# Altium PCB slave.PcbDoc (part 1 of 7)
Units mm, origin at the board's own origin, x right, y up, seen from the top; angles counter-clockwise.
Board outline 160 x 100 mm, 6 copper layers (Top, FUSED_VBAT-, Signals1, Signals2, SUPPLY, Bottom), stack 1.67 mm thick; 597 components, 381 nets, 1695 pads, 3028 vias.
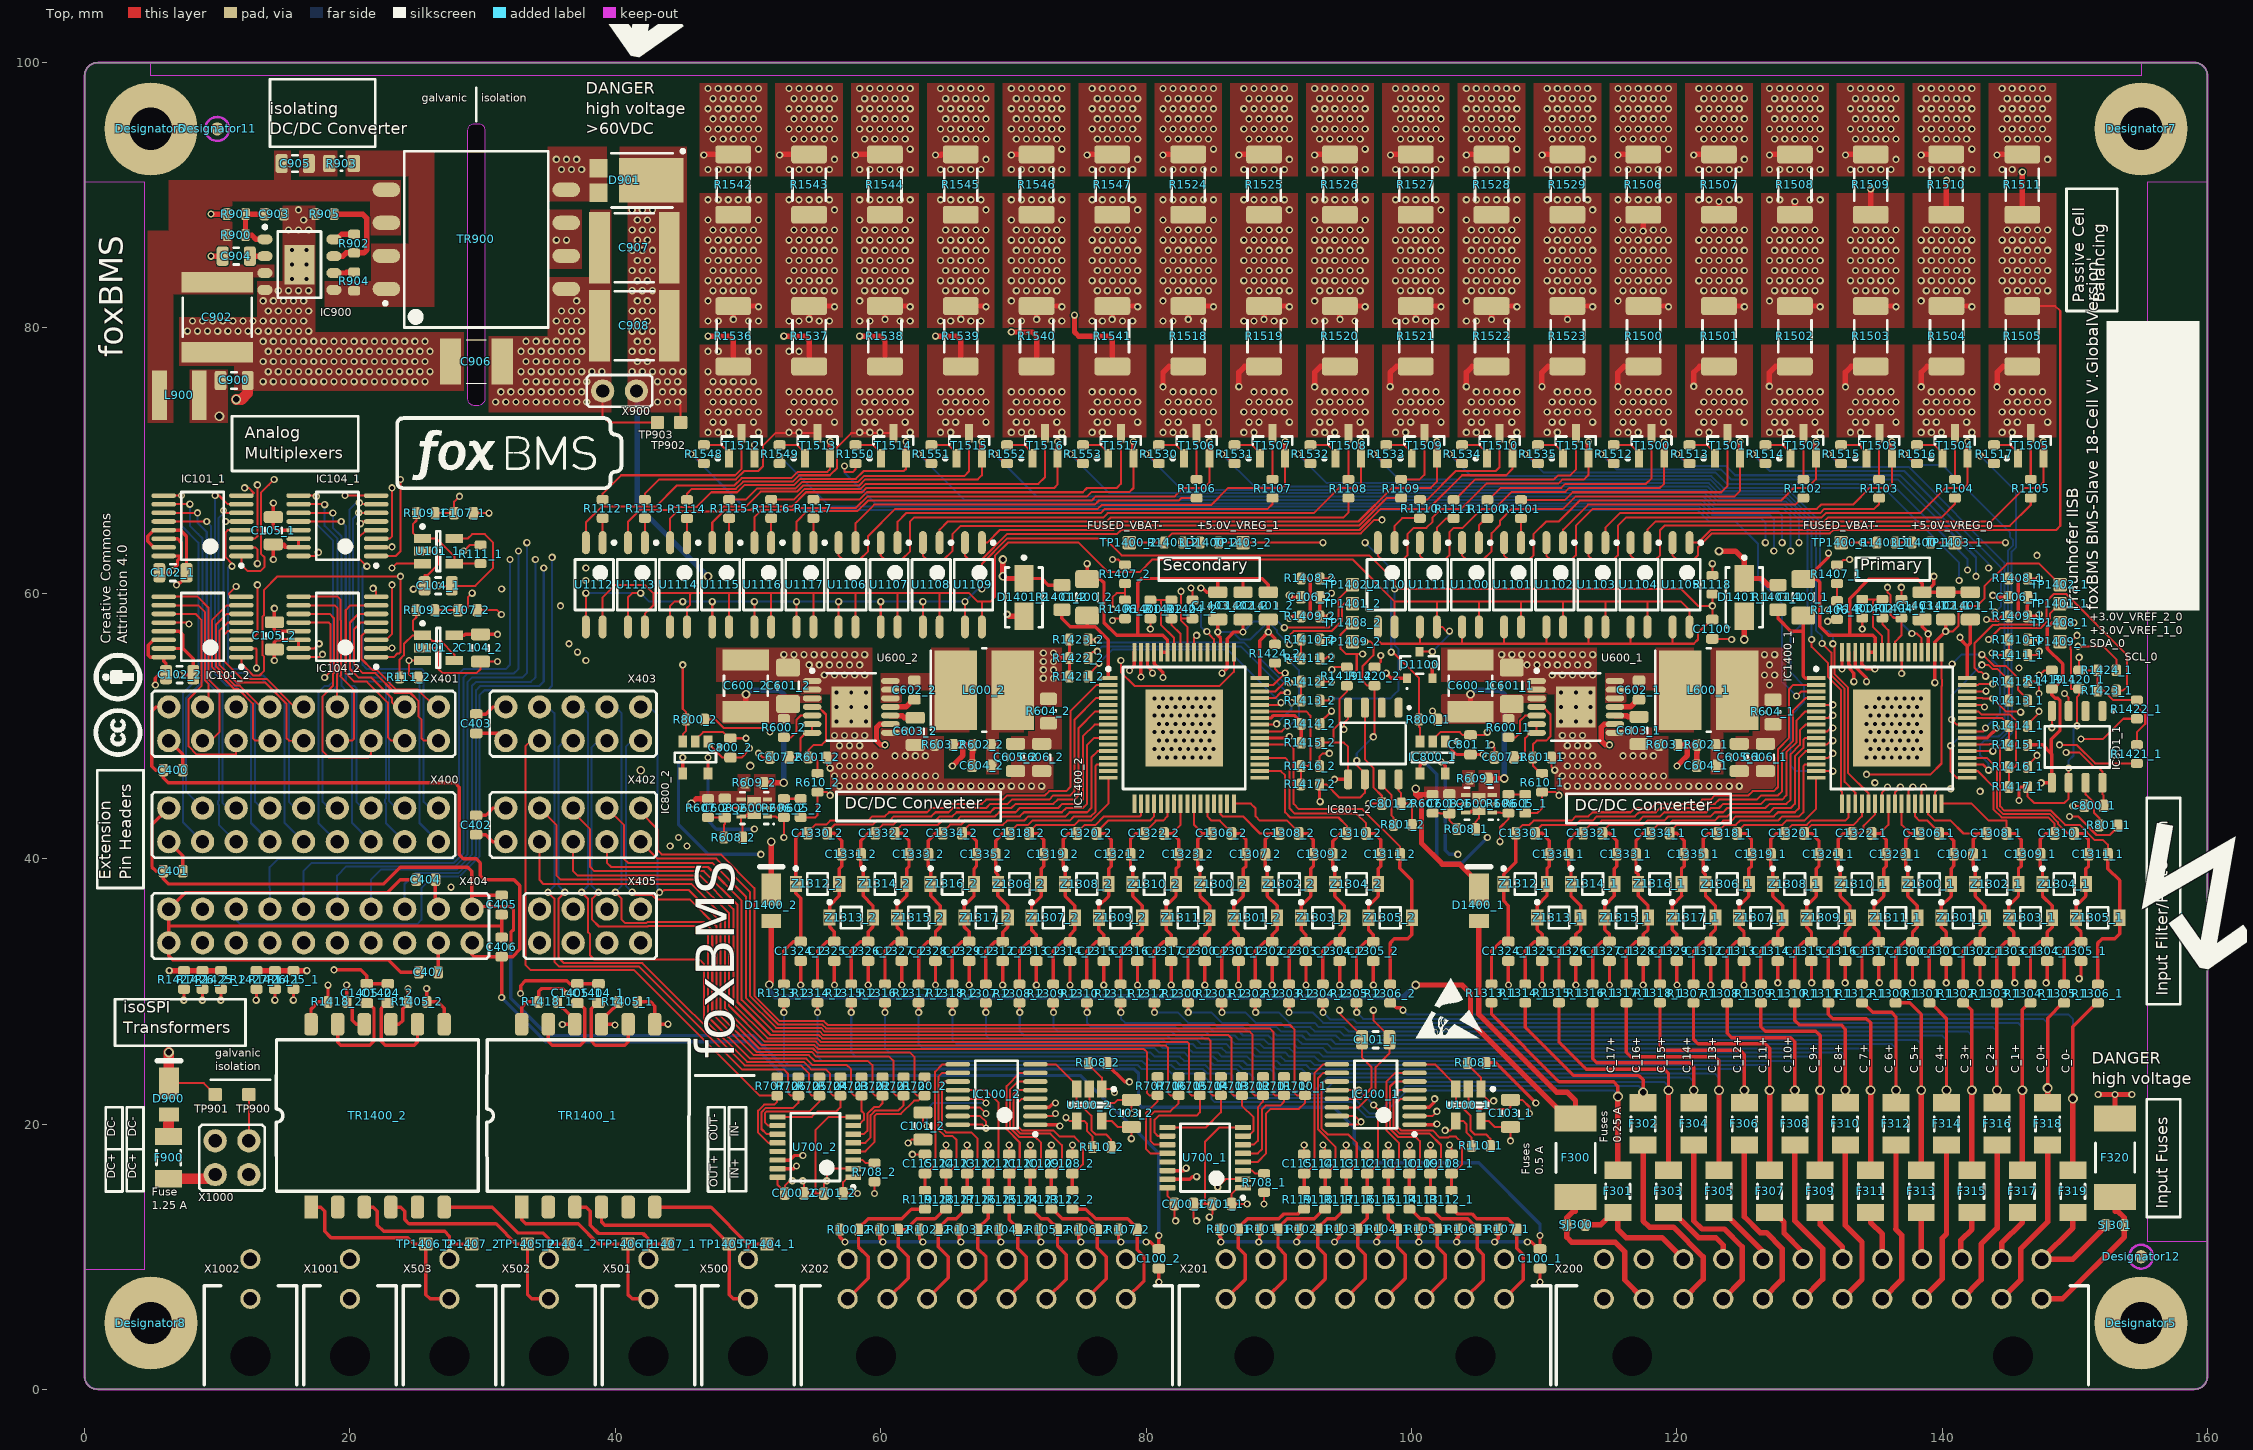
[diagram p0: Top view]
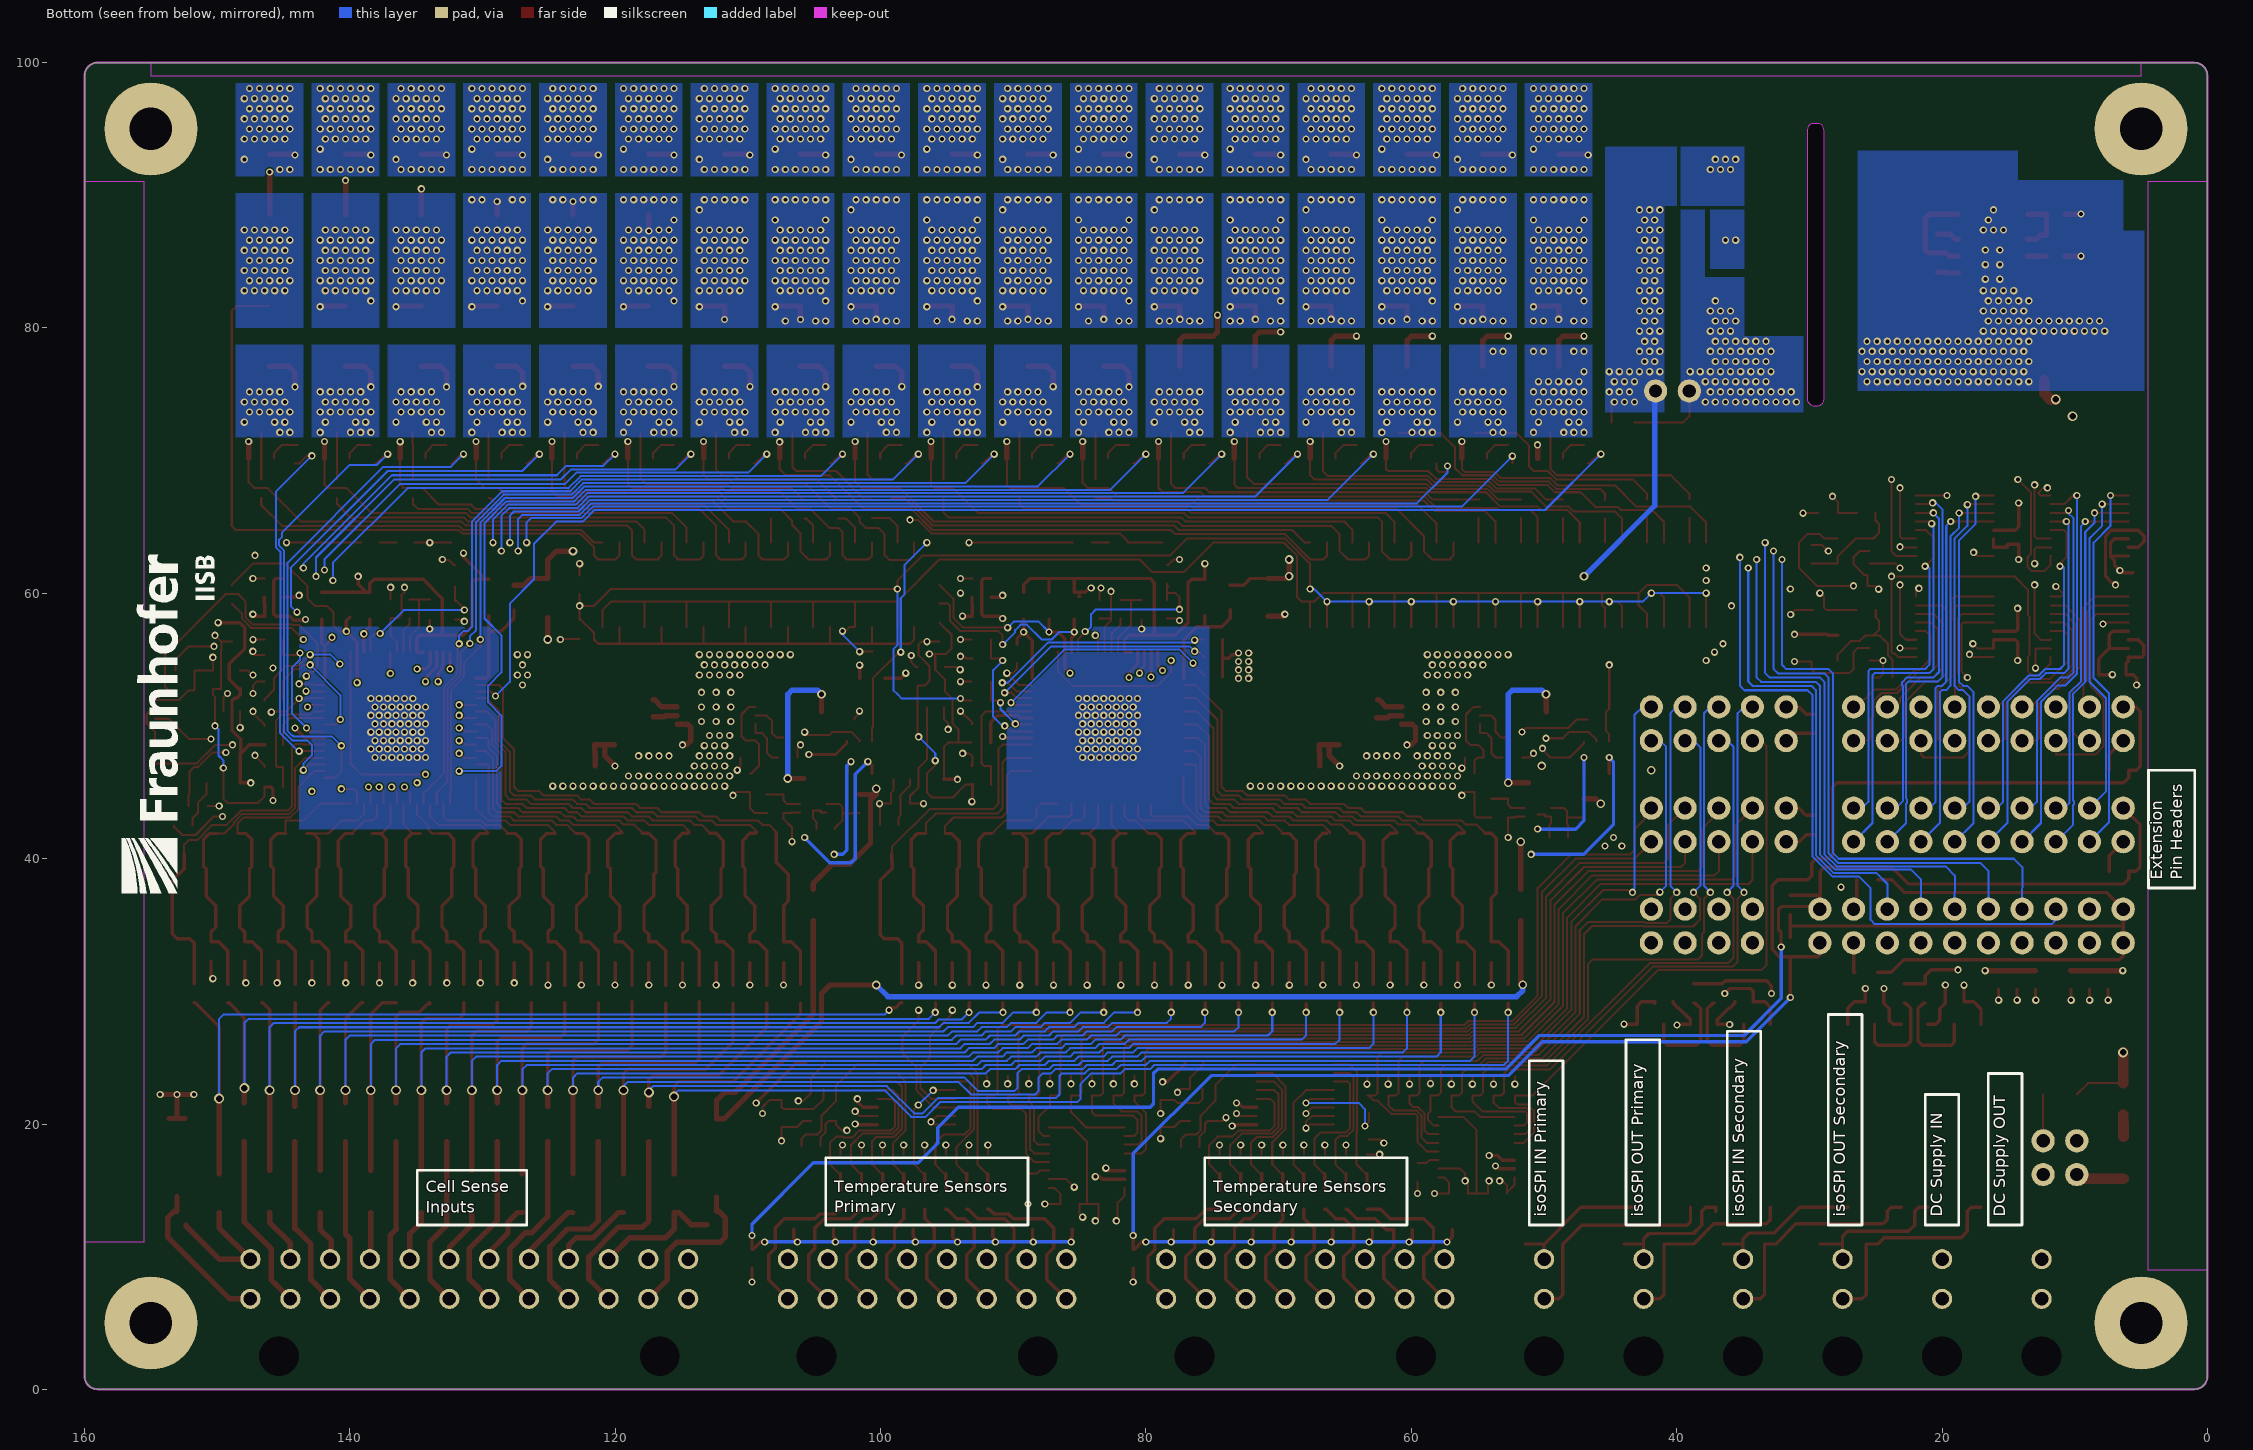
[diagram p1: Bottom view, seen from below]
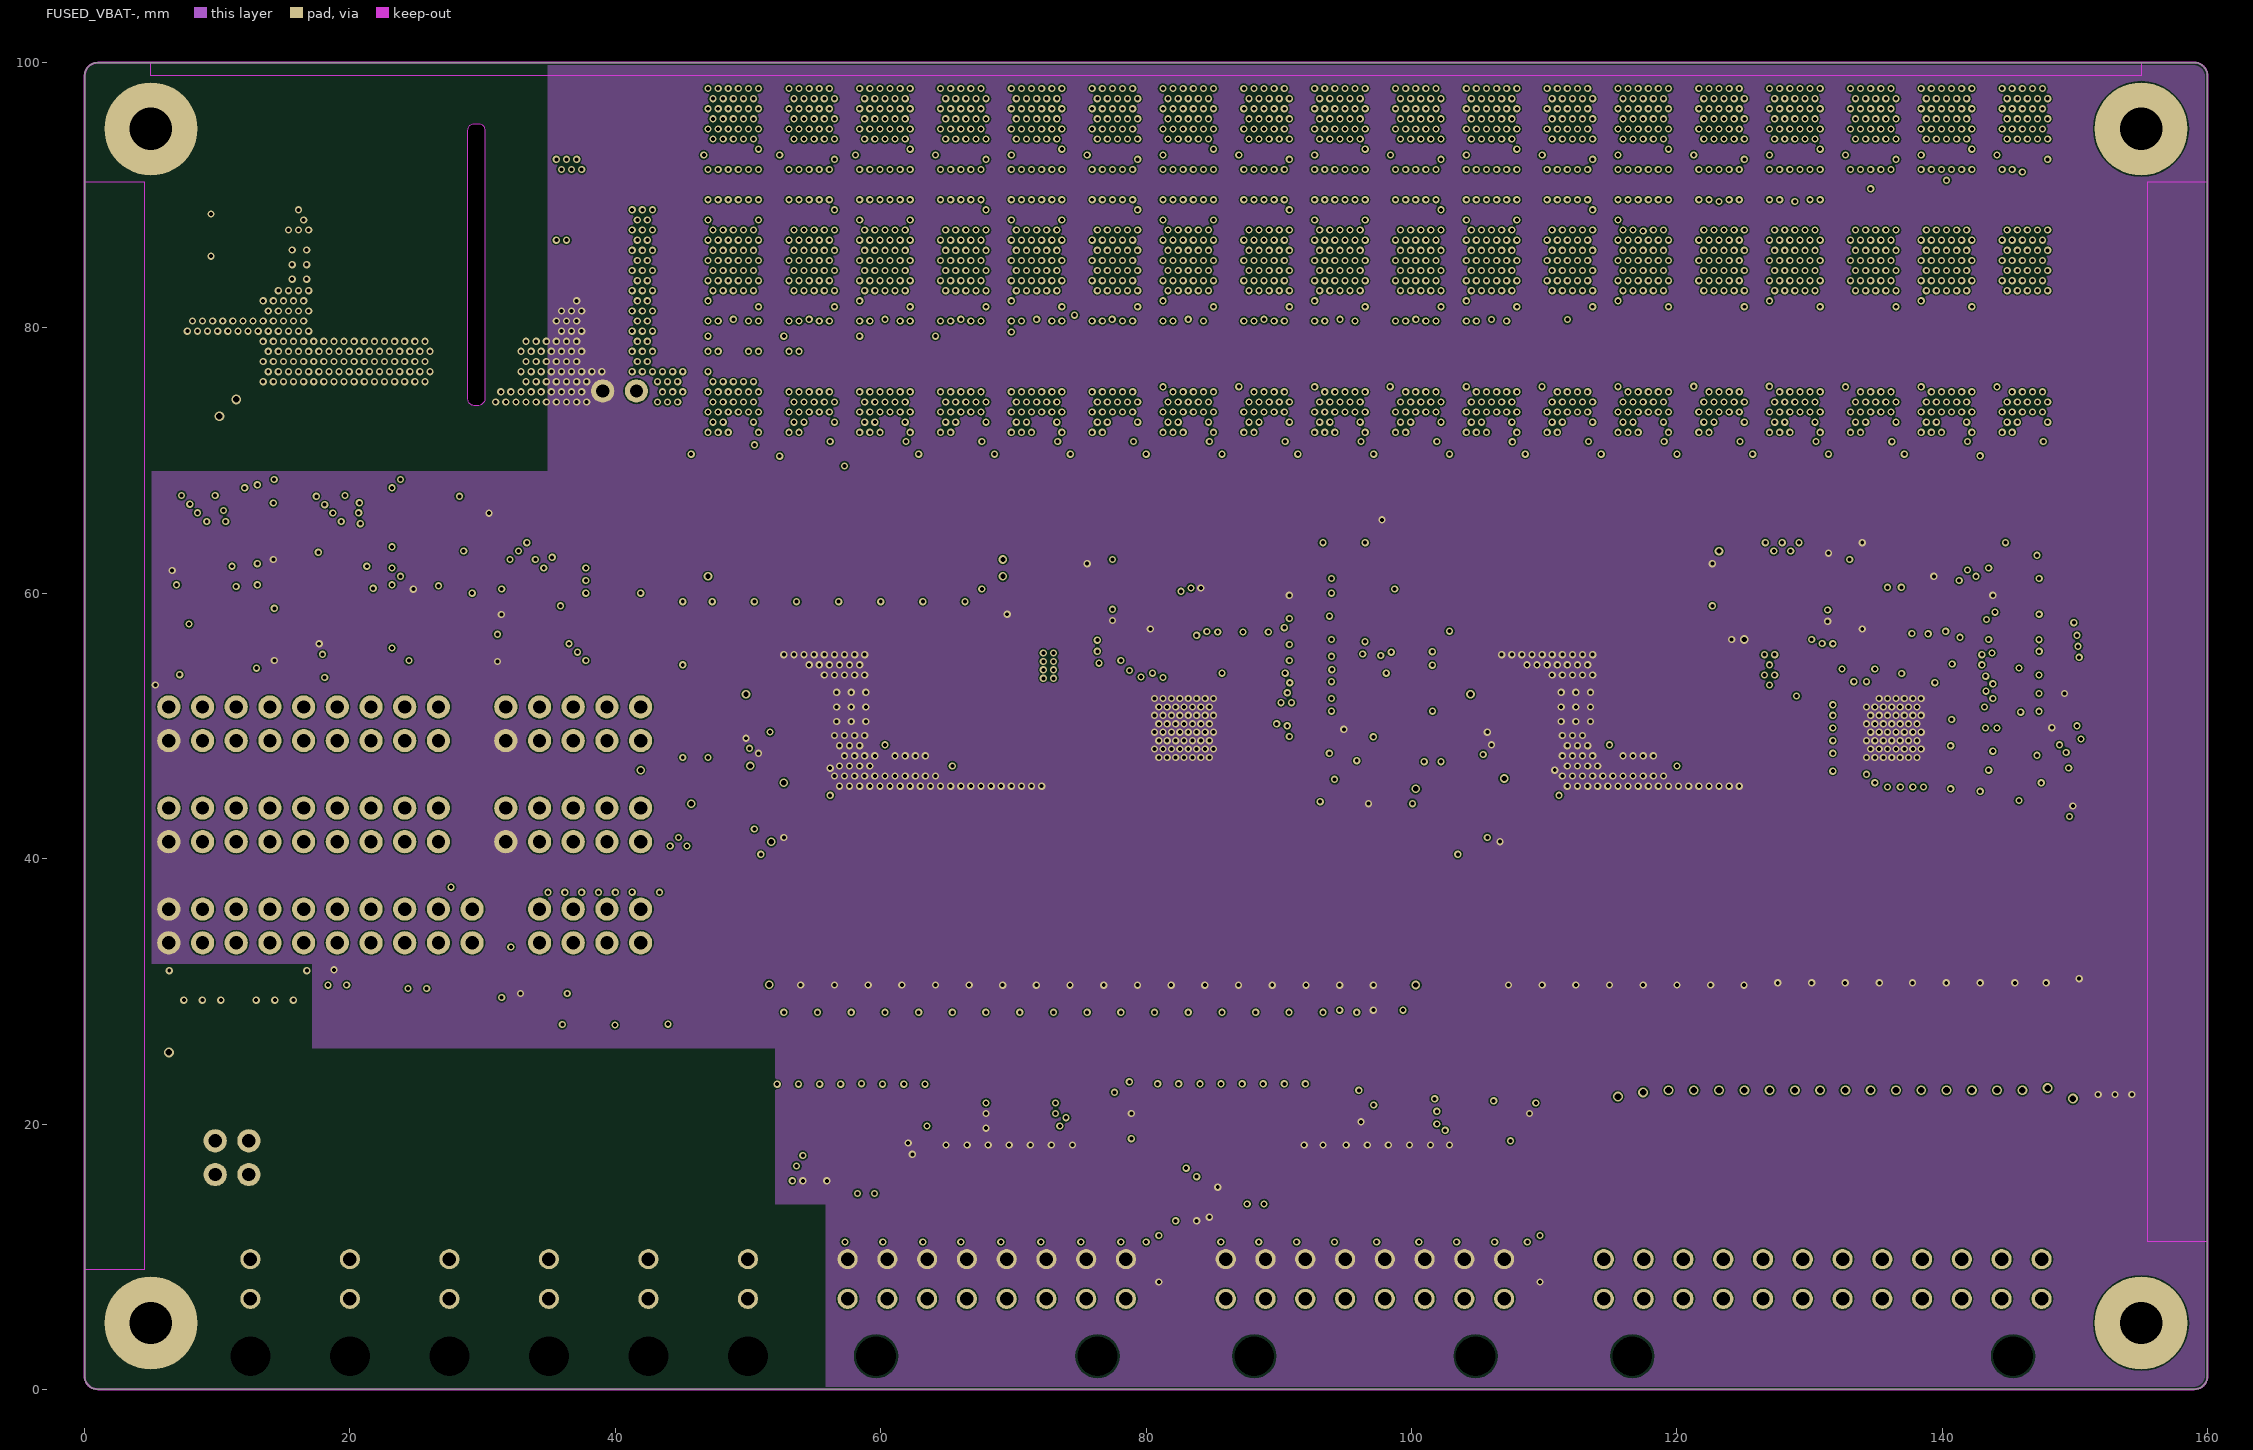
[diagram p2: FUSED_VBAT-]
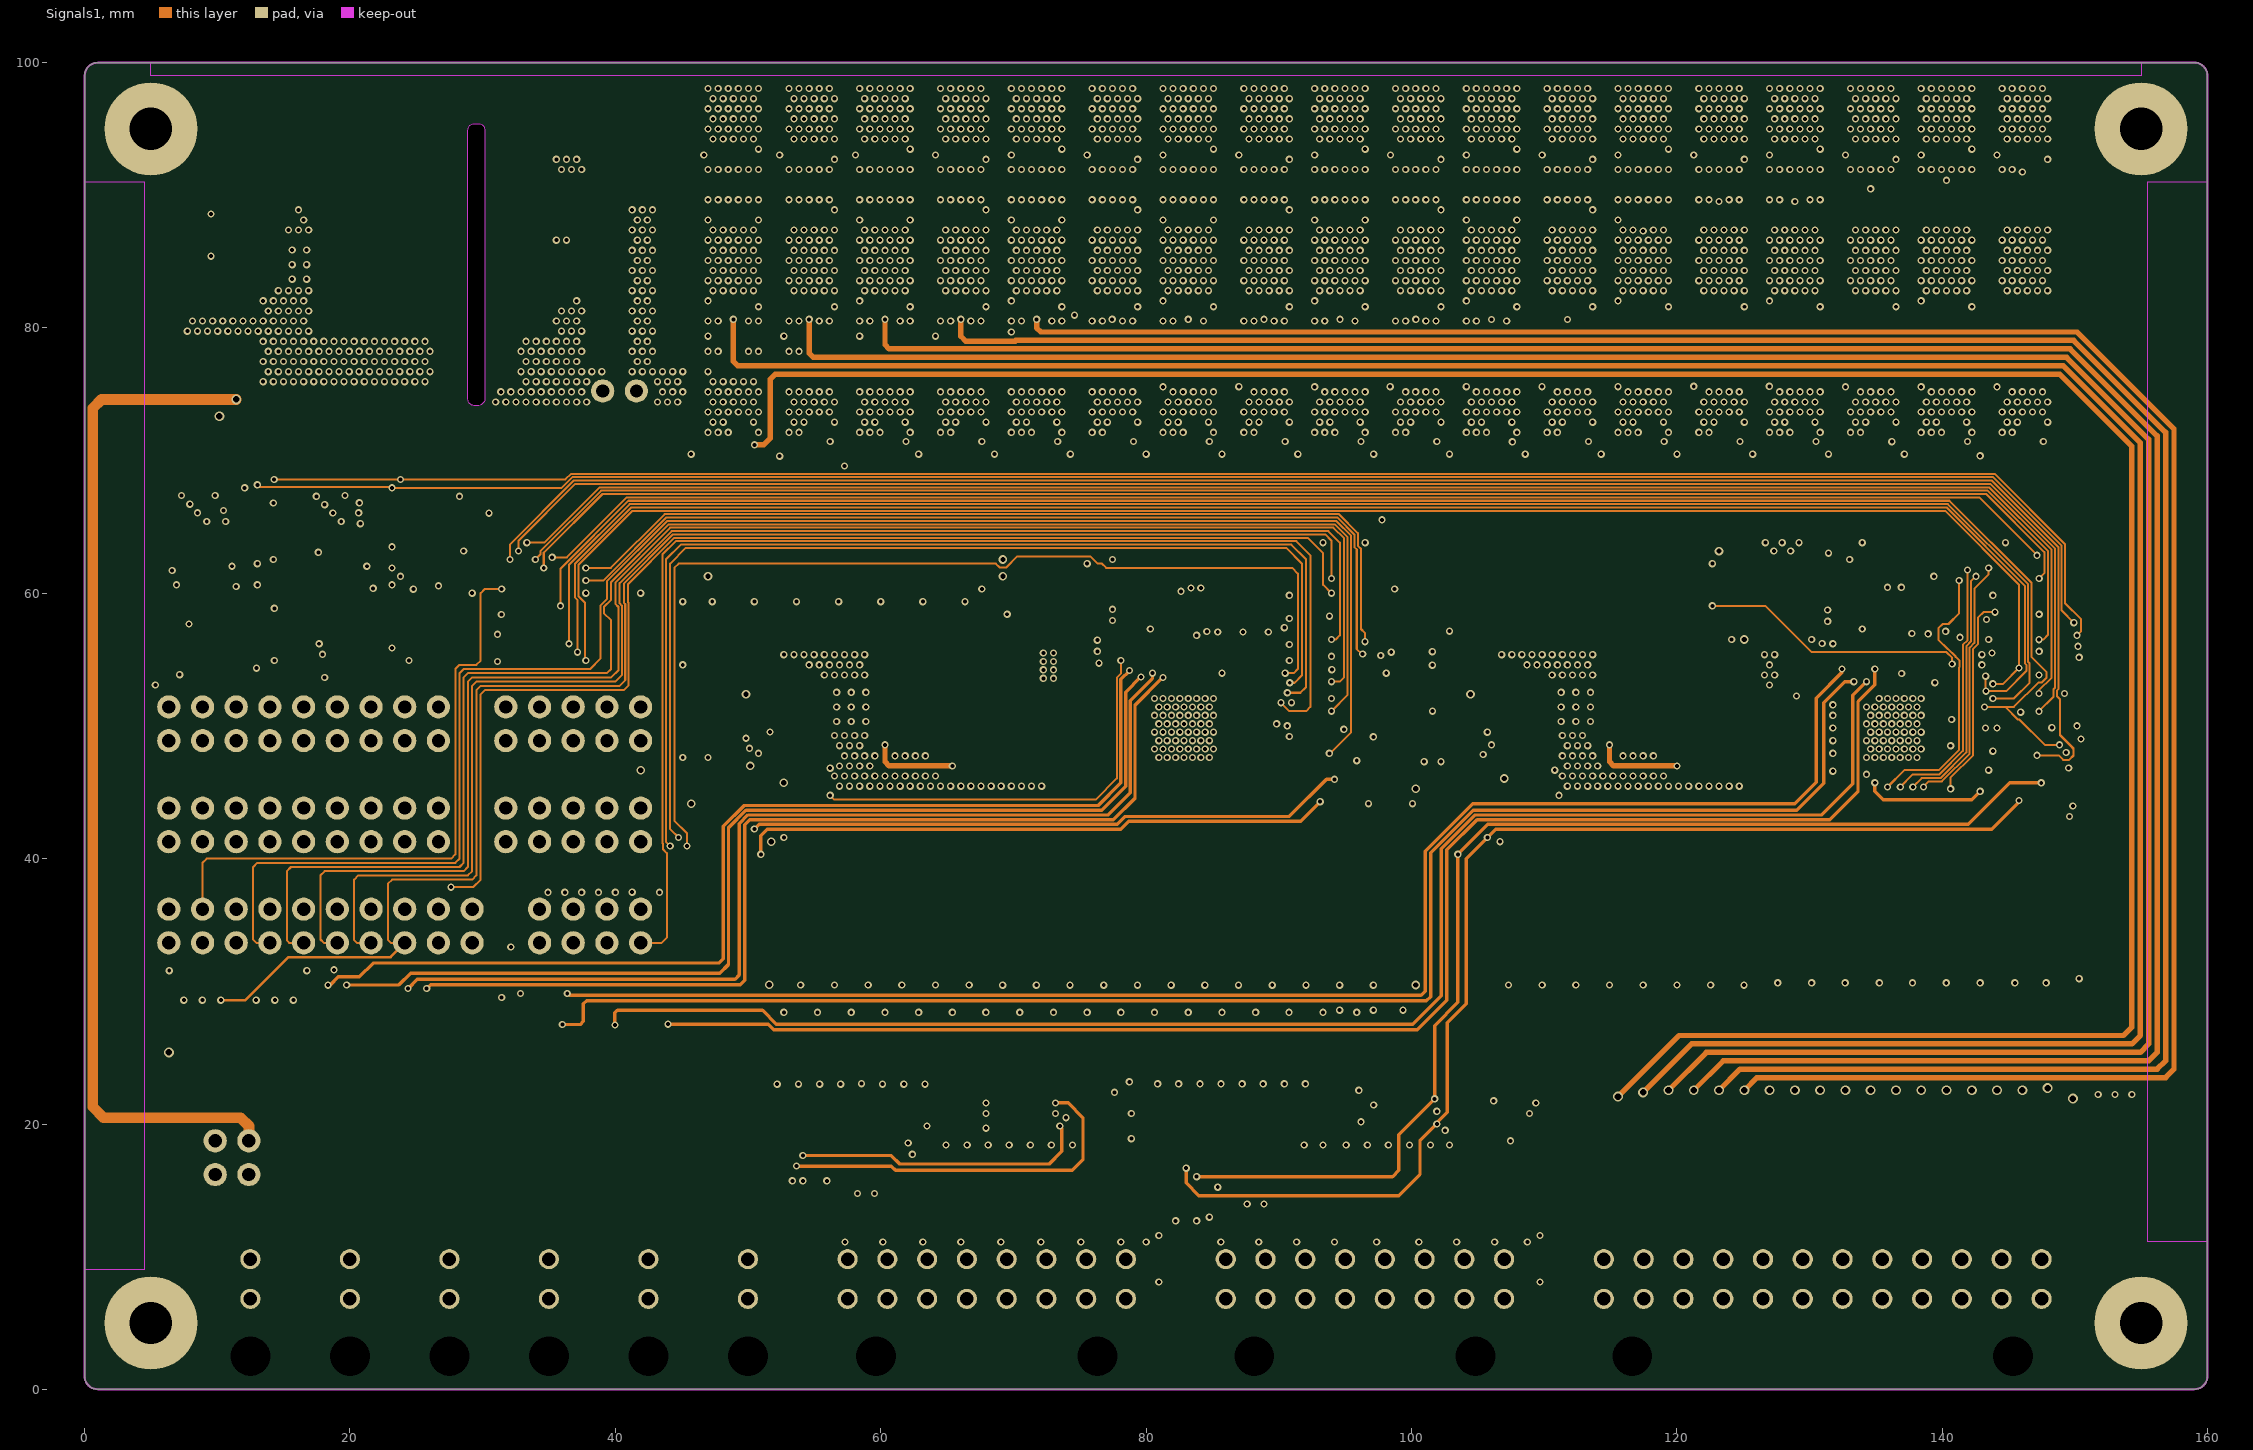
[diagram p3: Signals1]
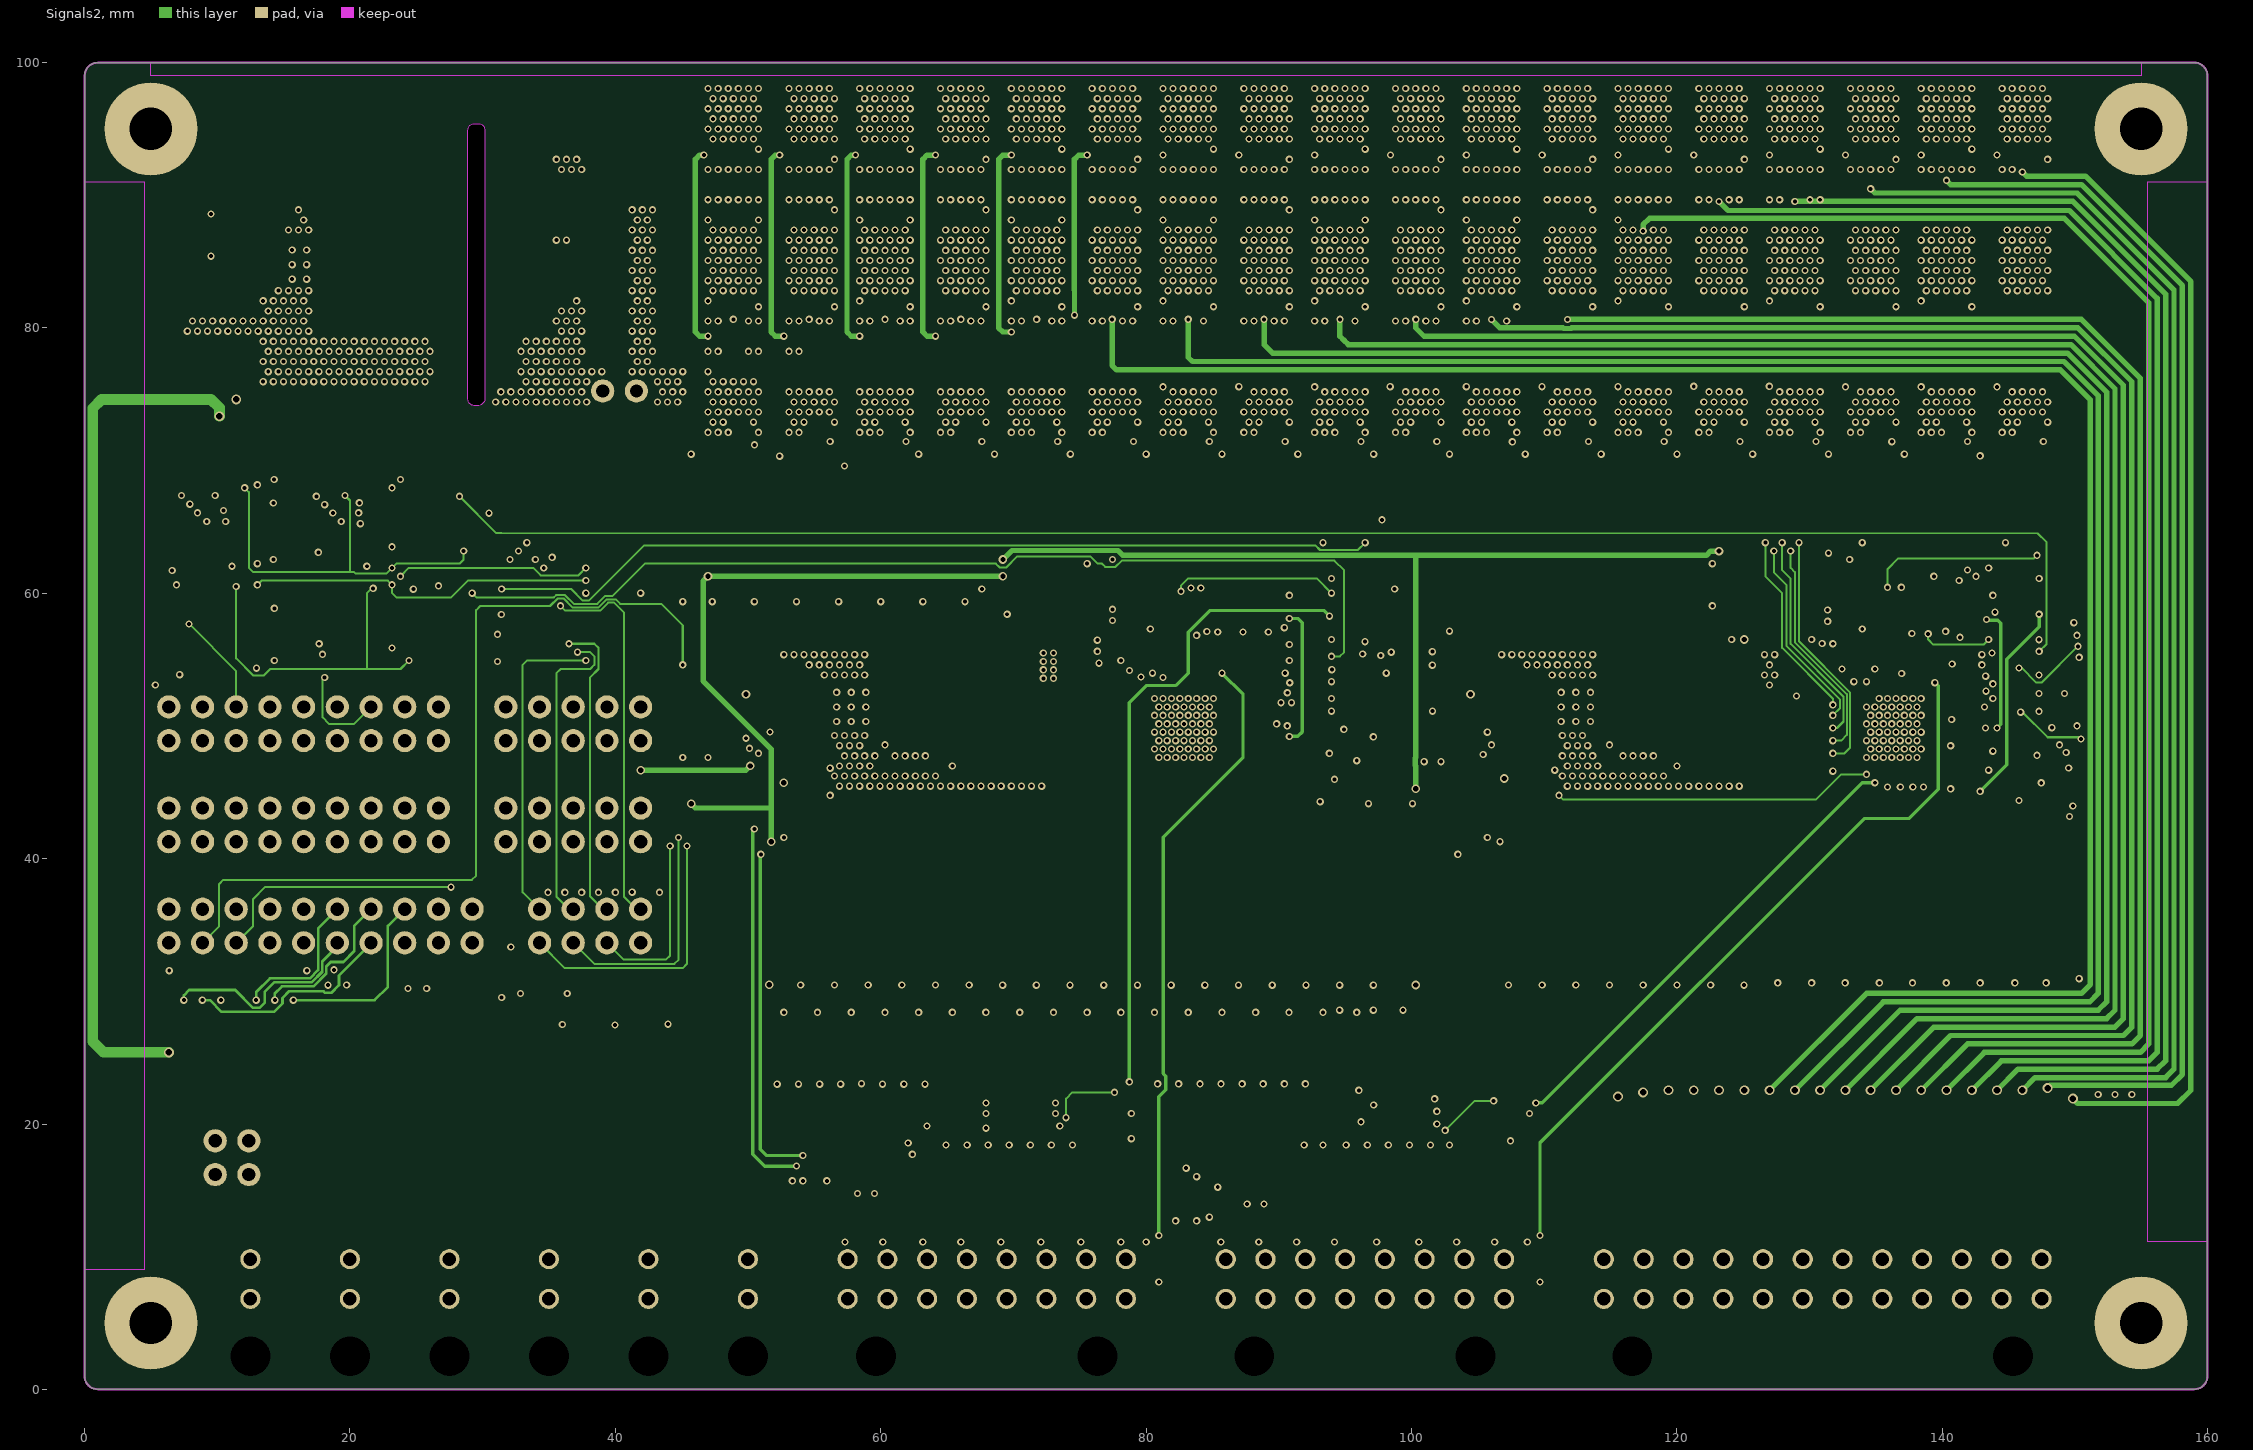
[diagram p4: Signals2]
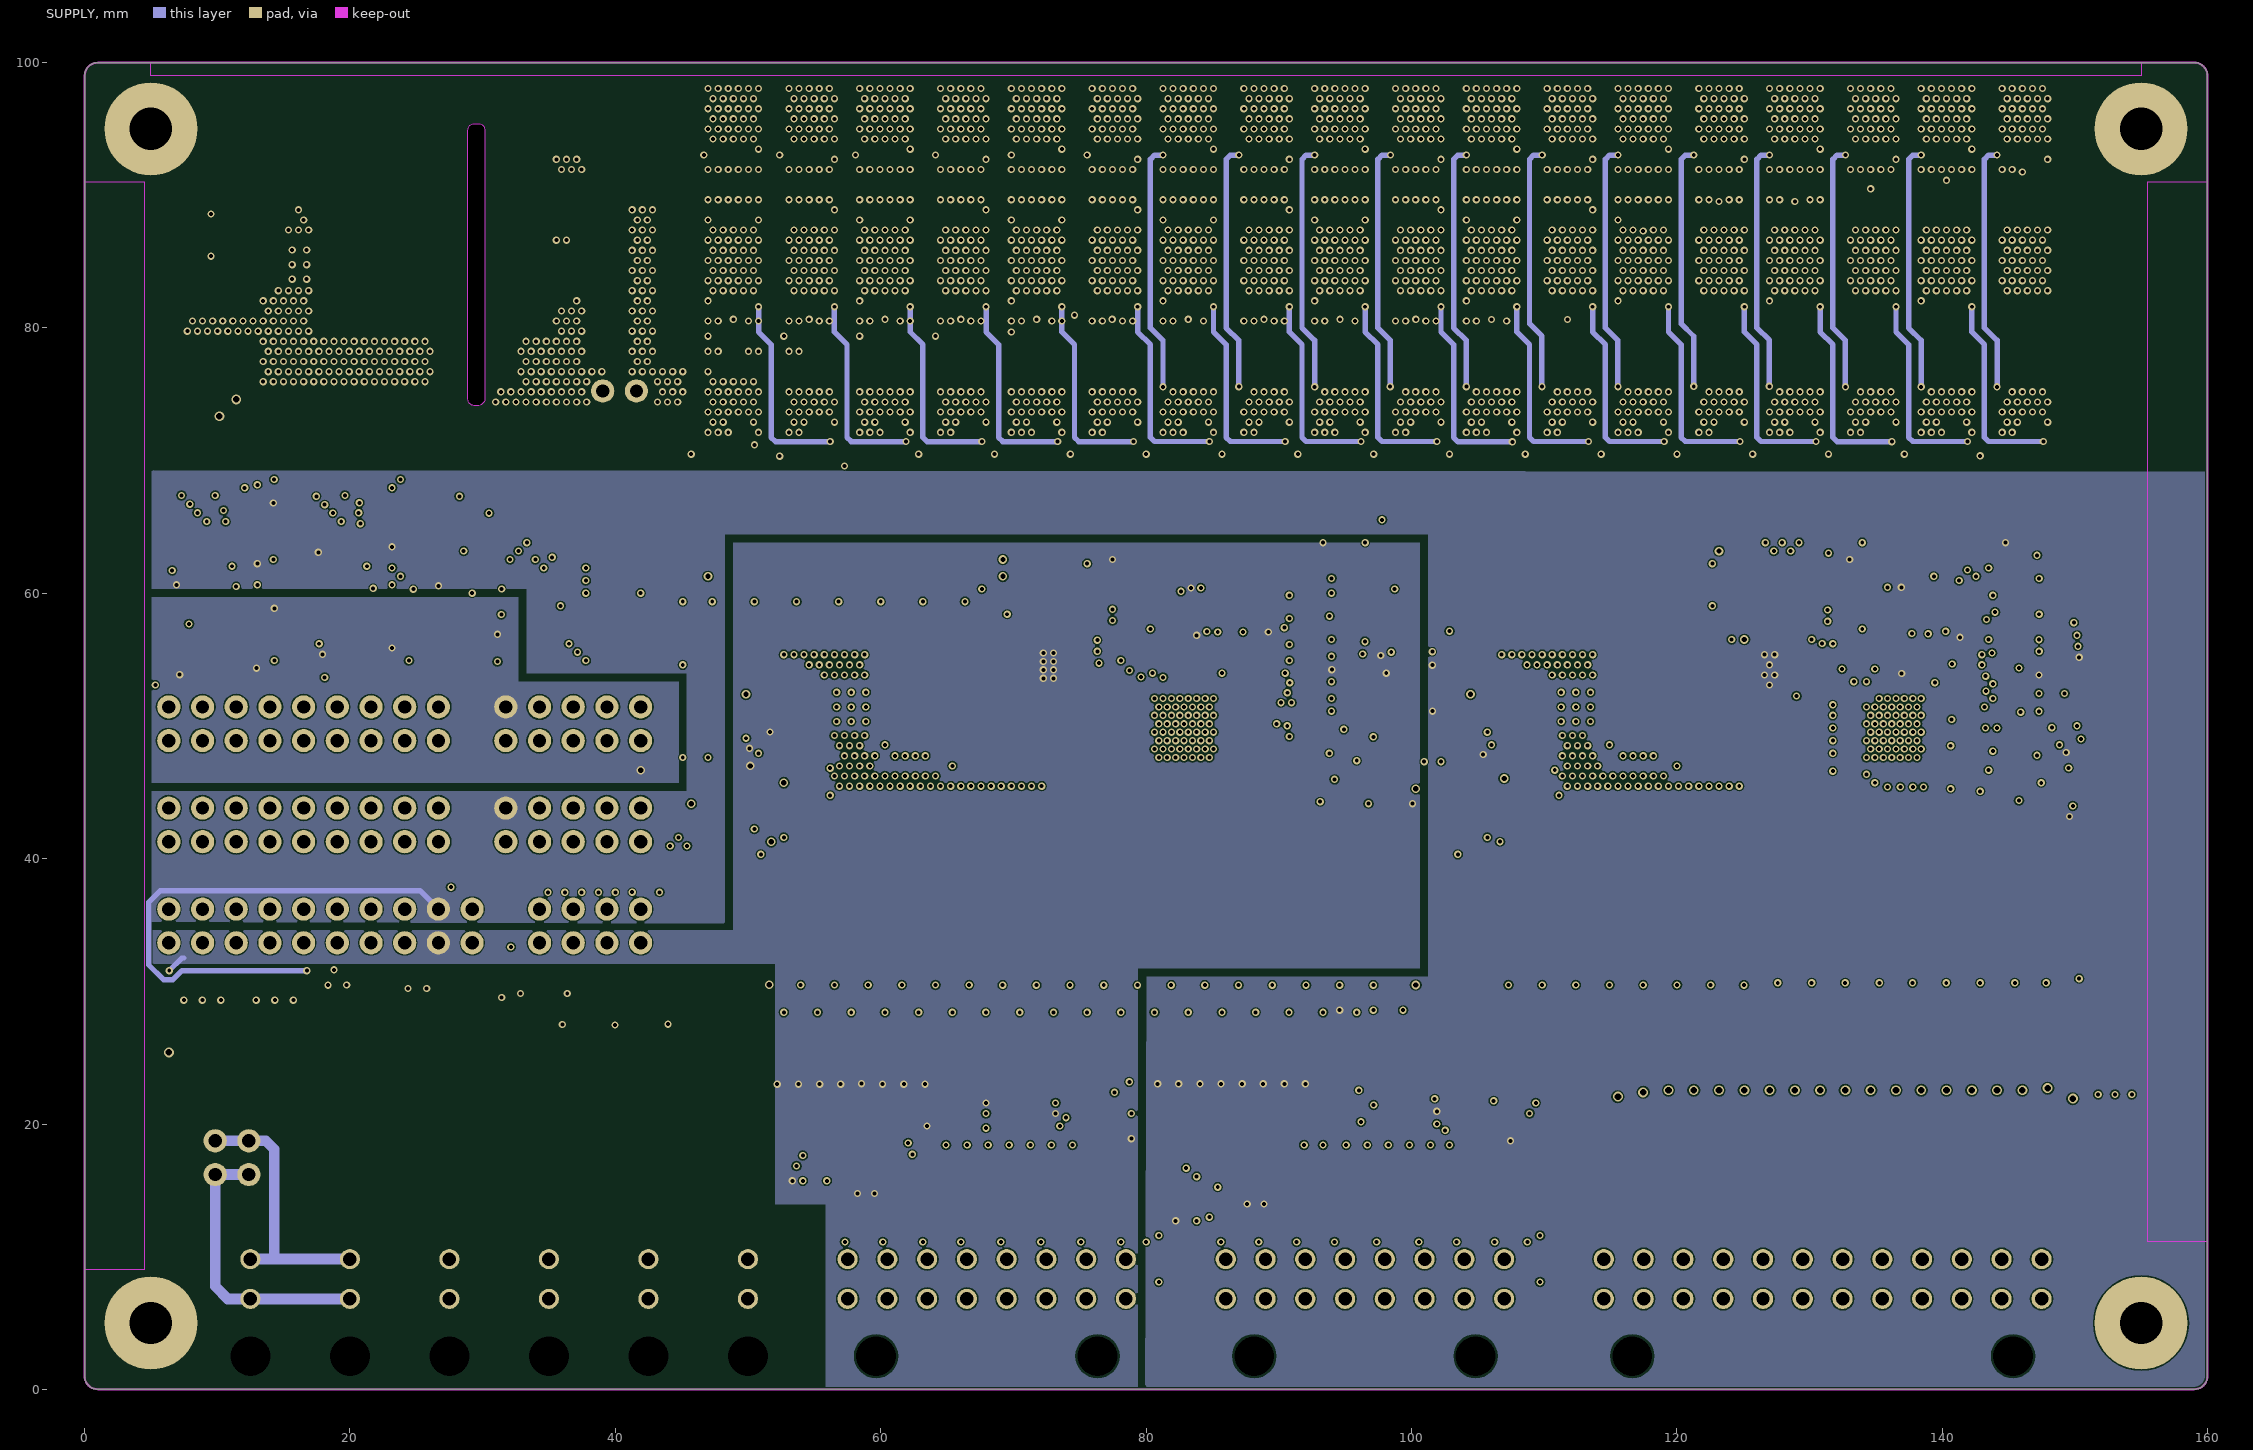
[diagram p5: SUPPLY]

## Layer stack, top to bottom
Top Solder: solder mask 0.015, Solder Resist, Dk 3.5
Top: signal copper 0.035
Dielectric 1: prepreg 0.2, FR-4, Dk 4.2
FUSED_VBAT-: signal copper 0.035
Dielectric2: core 0.35, FR-4, Dk 4.2
Signals1: signal copper 0.035
Dielectric3: prepreg 0.36, FR-4, Dk 4.2
Signals2: signal copper 0.035
Dielectric4: core 0.35, FR-4, Dk 4.2
SUPPLY: signal copper 0.035
Dielectric5: prepreg 0.2, FR-4, Dk 4.2
Bottom: signal copper 0.035
Bottom Solder: solder mask 0.015, Solder Resist, Dk 3.5

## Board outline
1,100 159,100 cw(c159,99) 160,99 160,1 cw(c159,1) 159,0 1,0 cw(c1,1) 0,1 0,99 cw(c1,99)
cut-out: 30.162,94.909 30.162,74.636 cw(c29.595,74.704) 29.527,74.136 29.393,74.136 cw(c29.393,74.636) 28.892,74.636 28.892,94.909 cw(c29.392,94.909) 29.393,95.409 29.663,95.409 cw(c29.663,94.909)

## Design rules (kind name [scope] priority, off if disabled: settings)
AssemblyTestPointUsage [All] p1 off:
AssemblyTestpoint [(IsPad And (OnTopLayer Or OnBottomLayer)) Or (IsPad And OnMultiLayer)] p1 off: testpointundercomponent=FALSE minsize=1.016 maxsize=2.54 preferedsize=1.524 minholesize=0 maxholesize=1.016 preferedholesize=0.813 testpointgrid=0.025 usegrid=TRUE gridtolerance=0 allowsidetop=TRUE
BoardOutlineClearance [All] p1: gap=0.203 ignorepadtopadclearanceinfootprint=FALSE except(0.508: Arc-CavityEdge Track-CavityEdge SMDPad-CavityEdge THPad-CavityEdge Via-CavityEdge Fill-CavityEdge Poly-CavityEdge Region-CavityEdge Text-CavityEdge)
Clearance "Stitching FUSED_CELL_10+" [IsStitchingVia and InNet('FUSED_CELL_10+') vs (IsVia and (Not IsStitchingVia)) Or IsPad] p1: gap=0.127 ignorepadtopadclearanceinfootprint=FALSE
Clearance [All] p2: gap=0.102 ignorepadtopadclearanceinfootprint=TRUE except(0.152: Arc-Text Arc-Hole Track-Text Track-Hole SMDPad-Text SMDPad-Hole THPad-Text THPad-Hole Via-Text Via-Hole Fill-Text Fill-Hole Poly-Text Poly-Hole Region-Text Region-Hole Text-Text Text-Hole; 0.203: Arc-Via Track-Via SMDPad-Via THPad-Via Via-Via)
FabricationTestpoint [All] p1: side=1 testpointundercomponent=TRUE minsize=0.508 maxsize=7.62 preferedsize=1.524 minholesize=0 maxholesize=1.016 preferedholesize=0.813 testpointgrid=0.025 allowsidetop=TRUE usegrid=FALSE gridtolerance=0
HoleSize [All] p1: absolutevalues=TRUE maxlimit=5.994 minlimit=0.2 maxpercent=80.000 minpercent=20.000
HoleToHoleClearance [All] p1: gap=0.152 allowstackedmicrovias=TRUE
MinimumAnnularRing [All] p1: minimumring=0.102
MinimumSolderMaskSliver [All] p1: minsoldermaskwidth=0.102
PlaneConnect [All] p1: planeconnectstyle=Direct reliefexpansion=0.508 reliefentries=4 reliefconductorwidth=0.254 reliefairgap=0.254
PolygonConnect [All] p1: connectstyle=Direct reliefconductorwidth=0.254 reliefentries=4 polygonreliefangle="90 Angle" airgapwidth=0.254
RoutingVias [All] p1: holewidth=0.203 width=0.45 viastyle="Through Hole" minholewidth=0.203 minwidth=0.45 maxholewidth=1 maxwidth=7 useviatemplates=TRUE viatemplateguid#1={0AB7DAA3-F58E-4780-A6E1-94A16C7095C0} viatemplateguid#2={26AB9DC0-33E3-4C9B-870D-B58389854110} viatemplateguid#3={9A71AE2B-4A20-477F-9082-EC06568001AF} viatemplatename#1=0.3mm_tented viatemplatename#2=0.4mm_tented viatemplatename#3=0.5mm_tented
SMDEntry [All] p1: side=TRUE corner=TRUE anyangle=FALSE
SMDToCorner [All] p1: distance=40000
SilkToSolderMaskClearance [IsPad] p1: minsilkscreentomaskgap=0.102 clearancetoexposedcopper=FALSE
SolderMaskExpansion SolderMaskExpansion_VIAs [IsVia] p1: expansion=-10 istentingtop=FALSE // Cover all Vias
SolderMaskExpansion [All] p2: expansion=0.051 istentingtop=FALSE
UnRoutedNet [All] p1: checkbadconnections=TRUE
UnpouredPolygon UnpouredPolygon_1 [All] p1:
Width [All] p1: maxlimit=1.524 minlimit=0.102 preferedwidth=0.152
20 further rules are at their usual default settings.

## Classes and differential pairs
channel class dcdc_converter: U_primary_dcdc_converter U_secondary_dcdc_converter
channel class eeprom_temp_sens: U_primary_eeprom_temp_sens U_secondary_eeprom_temp_sens
channel class digital_io: U_primary_digital_io U_secondary_digital_io
channel class analog_in: U_primary_analog_in U_secondary_analog_in
channel class LTC: U_primary_LTC U_secondary_LTC
channel class input_filter: U_primary_input_filter U_secondary_input_filter
polygon class PolygonThermal_ON_Width60000_Gap78740: Polygon_1_Net_+5.0V_VREG_1
polygon class Isolate_10: Polygon_1_Net_+5.0V_VREG_1
pad class SMDPaste_OFF: IC201-P$1 IC301-P$1

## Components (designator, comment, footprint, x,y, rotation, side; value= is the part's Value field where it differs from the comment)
C100_1 "100n/50V" CAPC1608X08N 109.696,9.842 r90 top (schematic designator C100)
C100_2 "100n/50V" CAPC1608X08N 80.962,9.842 r90 top (schematic designator C100)
C101_1 "1u/50V" CAPC2012X14N 97.314,26.352 r180 top (schematic designator C101)
C101_2 "1u/50V" CAPC2012X14N 63.182,19.844 r90 top (schematic designator C101)
C102_1 "1u/50V" CAPC2012X14N 6.655,61.552 r0 top (schematic designator C102)
C102_2 "1u/50V" CAPC2012X14N 7.166,53.868 r0 top (schematic designator C102)
C103_1 "1u/50V" CAPC2012X14N 107.474,20.796 r270 top (schematic designator C103)
C103_2 "1u/50V" CAPC2012X14N 78.899,20.796 r270 top (schematic designator C103)
C104_1 "1u/50V" CAPC2012X14N 26.65,60.567 r0 top (schematic designator C104)
C104_2 "1u/50V" CAPC2012X14N 29.845,55.88 r90 top (schematic designator C104)
C105_1 "1u/50V" CAPC2012X14N 14.224,64.718 r90 top (schematic designator C105)
C105_2 "1u/50V" CAPC2012X14N 14.306,56.793 r90 top (schematic designator C105)
C106_1 "10n/100V" CAPC1608X08N 145.732,59.69 r0 top (schematic designator C106)
C106_2 "10n/100V" CAPC1608X08N 92.392,59.69 r0 top (schematic designator C106)
C107_1 "10n/100V" CAPC1608X08N 28.575,66.04 r180 top (schematic designator C107)
C107_2 "10n/100V" CAPC1608X08N 28.872,58.725 r180 top (schematic designator C107)
C108_1 "10n/100V" CAPC1608X08N 103.029,16.986 r270 top (schematic designator C108)
C108_2 "10n/100V" CAPC1608X08N 74.454,16.986 r270 top (schematic designator C108)
C109_1 "10n/100V" CAPC1608X08N 101.441,16.986 r270 top (schematic designator C109)
C109_2 "10n/100V" CAPC1608X08N 72.866,16.986 r270 top (schematic designator C109)
C110_1 "10n/100V" CAPC1608X08N 99.854,16.986 r270 top (schematic designator C110)
C110_2 "10n/100V" CAPC1608X08N 71.279,16.986 r270 top (schematic designator C110)
C111_1 "10n/100V" CAPC1608X08N 98.266,16.986 r270 top (schematic designator C111)
C111_2 "10n/100V" CAPC1608X08N 69.691,16.986 r270 top (schematic designator C111)
C112_1 "10n/100V" CAPC1608X08N 96.679,16.986 r270 top (schematic designator C112)
C112_2 "10n/100V" CAPC1608X08N 68.104,16.986 r270 top (schematic designator C112)
C113_1 "10n/100V" CAPC1608X08N 95.091,16.986 r270 top (schematic designator C113)
C113_2 "10n/100V" CAPC1608X08N 66.516,16.986 r270 top (schematic designator C113)
C114_1 "10n/100V" CAPC1608X08N 93.504,16.986 r270 top (schematic designator C114)
C114_2 "10n/100V" CAPC1608X08N 64.929,16.986 r270 top (schematic designator C114)
C115_1 "10n/100V" CAPC1608X08N 91.916,16.986 r270 top (schematic designator C115)
C115_2 "10n/100V" CAPC1608X08N 63.341,16.986 r270 top (schematic designator C115)
C400 "100n/50V" CAPC1608X08N 6.667,46.672 r180 top
C401 "100n/50V" CAPC1608X08N 6.667,39.052 r180 top
C402 "100n/50V" CAPC1608X08N 29.507,42.533 r90 top
C403 "100n/50V" CAPC1608X08N 29.527,50.165 r90 top
C404 "100n/50V" CAPC1608X08N 25.717,38.417 r0 top
C405 "100n/50V" CAPC1608X08N 31.432,36.512 r90 top
C406 "100n/50V" CAPC1608X08N 31.432,33.337 r270 top
C407 "100n/50V" CAPC1608X08N 25.925,31.432 r0 top
C600_1 "1u/250V" CAPC4532X16N 104.457,53.023 r270 top (schematic designator C600)
C600_2 "1u/250V" CAPC4532X16N 49.847,53.023 r270 top (schematic designator C600)
C601_1 "100n/200V" CAPC3216X18N 107.569,53.023 r270 top (schematic designator C601)
C601_2 "100n/200V" CAPC3216X18N 53.023,53.023 r270 top (schematic designator C601)
C602_1 "100n/50V" CAPC1608X08N 117.157,52.705 r270 top locked (schematic designator C602)
C602_2 "100n/50V" CAPC1608X08N 62.547,52.705 r270 top locked (schematic designator C602)
C603_1 "1u/50V" CAPC2012X14N 117.157,49.657 r90 top locked (schematic designator C603)
C603_2 "1u/50V" CAPC2012X14N 62.611,49.593 r90 top locked (schematic designator C603)
C604_1 "100n/50V" CAPC1608X08N 122.237,46.99 r0 top (schematic designator C604)
C604_2 "100n/50V" CAPC1608X08N 67.627,46.99 r0 top (schematic designator C604)
C605_1 "2u2/10V" CAPC2012X14N 124.714,47.625 r90 top (schematic designator C605)
C605_2 "2u2/10V" CAPC2012X14N 70.168,47.625 r90 top (schematic designator C605)
C606_1 "2u2/10V" CAPC2012X14N 126.682,47.625 r90 top (schematic designator C606)
C606_2 "2u2/10V" CAPC2012X14N 72.136,47.625 r90 top (schematic designator C606)
C607_1 "100n/50V" CAPC1608X08N 106.998,47.625 r180 top locked (schematic designator C607)
C607_2 "100n/50V" CAPC1608X08N 52.387,47.625 r180 top locked (schematic designator C607)
C608_1 "10n/100V" CAPC1608X08N 102.87,44.133 r270 top (schematic designator C608)
C608_2 "10n/100V" CAPC1608X08N 48.26,43.815 r270 top (schematic designator C608)
C700_1 "100n/50V" CAPC1608X08N 82.867,13.97 r180 top locked (schematic designator C700)
C700_2 "100n/50V" CAPC1608X08N 53.499,14.764 r180 top (schematic designator C700)
C701_1 "100n/50V" CAPC1608X08N 85.725,13.97 r0 top (schematic designator C701)
C701_2 "100n/50V" CAPC1608X08N 56.455,14.764 r0 top (schematic designator C701)
C800_1 "100n/50V" CAPC1608X08N 151.447,43.974 r0 top (schematic designator C800)
C800_2 "100n/50V" CAPC1608X08N 48.677,48.35 r270 top (schematic designator C800)
C801_1 "100n/50V" CAPC1608X08N 104.457,48.578 r270 top (schematic designator C801)
C801_2 "100n/50V" CAPC1608X08N 98.51,44.147 r0 top (schematic designator C801)
C900 "1u/50V" CAPC2012X14N 11.271,76.041 r180 top
C902 "22u/50V" CAPC2220(5750)230_N 10.001,80.804 r90 top
C903 "100n/50V" CAPC1608X08N 14.287,88.582 r180 top
C904 "1u/50V" CAPC2012X14N 11.43,85.407 r0 top
C905 "470p/100V" CAPC2012X14N 15.875,92.392 r180 top
C906 "4n7/1000V" CAPC4532X16N 29.527,77.47 r0 top locked
C907 "2u2/250V" CAPC2220(5750)230_N 41.434,86.042 r0 top locked
C908 "2u2/250V" CAPC2220(5750)230_N 41.434,80.169 r0 top locked
C1100 "100n/50V" CAPC1608X08N 122.687,57.291 r90 top
C1300_1 "10n/100V" CAPC1608X08N 137.775,33.008 r270 top (schematic designator C1300)
C1300_2 "10n/100V" CAPC1608X08N 84.435,33.008 r270 top (schematic designator C1300)
C1301_1 "10n/100V" CAPC1608X08N 140.315,33.008 r270 top (schematic designator C1301)
C1301_2 "10n/100V" CAPC1608X08N 86.975,33.008 r270 top (schematic designator C1301)
C1302_1 "10n/100V" CAPC1608X08N 142.855,33.008 r270 top (schematic designator C1302)
C1302_2 "10n/100V" CAPC1608X08N 89.515,33.008 r270 top (schematic designator C1302)
C1303_1 "10n/100V" CAPC1608X08N 145.395,33.008 r270 top (schematic designator C1303)
C1303_2 "10n/100V" CAPC1608X08N 92.055,33.008 r270 top (schematic designator C1303)
C1304_1 "10n/100V" CAPC1608X08N 147.935,33.008 r270 top (schematic designator C1304)
C1304_2 "10n/100V" CAPC1608X08N 94.595,33.008 r270 top (schematic designator C1304)
C1305_1 "10n/100V" CAPC1608X08N 150.475,33.008 r270 top (schematic designator C1305)
C1305_2 "10n/100V" CAPC1608X08N 97.135,33.008 r270 top (schematic designator C1305)
C1306_1 "10n/100V" CAPC1608X08N 139.045,41.898 r0 top (schematic designator C1306)
C1306_2 "10n/100V" CAPC1608X08N 85.705,41.898 r0 top (schematic designator C1306)
C1307_1 "10n/100V" CAPC1608X08N 141.617,40.322 r0 top (schematic designator C1307)
C1307_2 "10n/100V" CAPC1608X08N 88.265,40.322 r0 top (schematic designator C1307)
C1308_1 "10n/100V" CAPC1608X08N 144.125,41.898 r0 top (schematic designator C1308)
C1308_2 "10n/100V" CAPC1608X08N 90.785,41.898 r0 top (schematic designator C1308)
C1309_1 "10n/100V" CAPC1608X08N 146.685,40.322 r0 top (schematic designator C1309)
C1309_2 "10n/100V" CAPC1608X08N 93.345,40.322 r0 top (schematic designator C1309)
C1310_1 "10n/100V" CAPC1608X08N 149.205,41.898 r0 top (schematic designator C1310)
C1310_2 "10n/100V" CAPC1608X08N 95.865,41.898 r0 top (schematic designator C1310)
C1311_1 "10n/100V" CAPC1608X08N 151.765,40.322 r0 top (schematic designator C1311)
C1311_2 "10n/100V" CAPC1608X08N 98.425,40.322 r0 top (schematic designator C1311)
C1312_1 "10n/100V" CAPC1608X08N 122.555,33.02 r270 top (schematic designator C1312)
C1312_2 "10n/100V" CAPC1608X08N 69.195,33.008 r270 top (schematic designator C1312)
C1313_1 "10n/100V" CAPC1608X08N 125.075,33.008 r270 top (schematic designator C1313)
C1313_2 "10n/100V" CAPC1608X08N 71.735,33.008 r270 top (schematic designator C1313)
C1314_1 "10n/100V" CAPC1608X08N 127.615,33.008 r270 top (schematic designator C1314)
C1314_2 "10n/100V" CAPC1608X08N 74.275,33.008 r270 top (schematic designator C1314)
C1315_1 "10n/100V" CAPC1608X08N 130.155,33.008 r270 top (schematic designator C1315)
C1315_2 "10n/100V" CAPC1608X08N 76.815,33.008 r270 top (schematic designator C1315)
C1316_1 "10n/100V" CAPC1608X08N 132.695,33.008 r270 top (schematic designator C1316)
C1316_2 "10n/100V" CAPC1608X08N 79.355,33.008 r270 top (schematic designator C1316)
C1317_1 "10n/100V" CAPC1608X08N 135.235,33.008 r270 top (schematic designator C1317)
C1317_2 "10n/100V" CAPC1608X08N 81.895,33.008 r270 top (schematic designator C1317)
C1318_1 "10n/100V" CAPC1608X08N 123.805,41.898 r0 top (schematic designator C1318)
C1318_2 "10n/100V" CAPC1608X08N 70.465,41.898 r0 top (schematic designator C1318)
C1319_1 "10n/100V" CAPC1608X08N 126.365,40.322 r0 top (schematic designator C1319)
C1319_2 "10n/100V" CAPC1608X08N 73.025,40.322 r0 top (schematic designator C1319)
C1320_1 "10n/100V" CAPC1608X08N 128.885,41.898 r0 top (schematic designator C1320)
C1320_2 "10n/100V" CAPC1608X08N 75.545,41.898 r0 top (schematic designator C1320)
C1321_1 "10n/100V" CAPC1608X08N 131.445,40.322 r0 top (schematic designator C1321)
C1321_2 "10n/100V" CAPC1608X08N 78.105,40.322 r0 top (schematic designator C1321)
C1322_1 "10n/100V" CAPC1608X08N 133.965,41.898 r0 top (schematic designator C1322)
C1322_2 "10n/100V" CAPC1608X08N 80.625,41.898 r0 top (schematic designator C1322)
C1323_1 "10n/100V" CAPC1608X08N 136.525,40.322 r0 top (schematic designator C1323)
C1323_2 "10n/100V" CAPC1608X08N 83.185,40.322 r0 top (schematic designator C1323)
C1324_1 "10n/100V" CAPC1608X08N 107.315,33.02 r270 top (schematic designator C1324)
C1324_2 "10n/100V" CAPC1608X08N 53.975,33.02 r270 top (schematic designator C1324)
C1325_1 "10n/100V" CAPC1608X08N 109.855,33.02 r270 top (schematic designator C1325)
C1325_2 "10n/100V" CAPC1608X08N 56.515,33.02 r270 top (schematic designator C1325)
C1326_1 "10n/100V" CAPC1608X08N 112.395,33.02 r270 top (schematic designator C1326)
C1326_2 "10n/100V" CAPC1608X08N 59.055,33.02 r270 top (schematic designator C1326)
C1327_1 "10n/100V" CAPC1608X08N 114.935,33.02 r270 top (schematic designator C1327)
C1327_2 "10n/100V" CAPC1608X08N 61.595,33.02 r270 top (schematic designator C1327)
C1328_1 "10n/100V" CAPC1608X08N 117.475,33.02 r270 top (schematic designator C1328)
C1328_2 "10n/100V" CAPC1608X08N 64.135,33.02 r270 top (schematic designator C1328)
C1329_1 "10n/100V" CAPC1608X08N 120.015,33.02 r270 top (schematic designator C1329)
C1329_2 "10n/100V" CAPC1608X08N 66.675,33.02 r270 top (schematic designator C1329)
C1330_1 "10n/100V" CAPC1608X08N 108.585,41.91 r0 top (schematic designator C1330)
C1330_2 "10n/100V" CAPC1608X08N 55.245,41.91 r0 top (schematic designator C1330)
C1331_1 "10n/100V" CAPC1608X08N 111.125,40.322 r0 top (schematic designator C1331)
C1331_2 "10n/100V" CAPC1608X08N 57.785,40.322 r0 top (schematic designator C1331)
C1332_1 "10n/100V" CAPC1608X08N 113.665,41.91 r0 top (schematic designator C1332)
C1332_2 "10n/100V" CAPC1608X08N 60.325,41.91 r0 top (schematic designator C1332)
C1333_1 "10n/100V" CAPC1608X08N 116.205,40.322 r0 top (schematic designator C1333)
C1333_2 "10n/100V" CAPC1608X08N 62.865,40.322 r0 top (schematic designator C1333)
C1334_1 "10n/100V" CAPC1608X08N 118.745,41.91 r0 top (schematic designator C1334)
C1334_2 "10n/100V" CAPC1608X08N 65.405,41.91 r0 top (schematic designator C1334)
C1335_1 "10n/100V" CAPC1608X08N 121.285,40.322 r0 top (schematic designator C1335)
C1335_2 "10n/100V" CAPC1608X08N 67.945,40.322 r0 top (schematic designator C1335)
C1400_1 "100n/200V" CAPC3216X18N 129.54,59.69 r90 top locked (schematic designator C1400)
C1400_2 "100n/200V" CAPC3216X18N 75.565,59.69 r90 top (schematic designator C1400)
C1401_1 "1u/50V" CAPC2012X14N 142.13,59.055 r270 top (schematic designator C1401)
C1401_2 "1u/50V" CAPC2012X14N 89.218,59.055 r270 top (schematic designator C1401)
C1402_1 "1u/50V" CAPC2012X14N 140.272,59.055 r270 top (schematic designator C1402)
C1402_2 "1u/50V" CAPC2012X14N 87.312,59.055 r270 top (schematic designator C1402)
C1403_1 "1u/50V" CAPC2012X14N 138.493,59.055 r270 top locked (schematic designator C1403)
C1403_2 "1u/50V" CAPC2012X14N 85.407,59.055 r270 top locked (schematic designator C1403)
C1404_1 "100p/50V" CAPC1608X08N 38.735,29.845 r270 top (schematic designator C1404)
C1404_2 "100p/50V" CAPC1608X08N 22.86,29.845 r270 top (schematic designator C1404)
C1405_1 "100p/50V" CAPC1608X08N 37.148,29.845 r270 top (schematic designator C1405)
C1405_2 "100p/50V" CAPC1608X08N 21.273,29.845 r270 top locked (schematic designator C1405)
D900 "DFLS1100-7" DIOD-POWERDI123-2_V 6.35,22.225 r90 top locked
D901 "PDS3200" PowerDI5 41.593,91.123 r0 top locked
D1100 "BAT54C,215" NXP-SOT23-3_V 100.627,54.598 r180 top
D1400_1 "DFLS1100-7" DIOD-POWERDI123-2_V 105.093,36.83 r90 top (schematic designator D1400)
D1400_2 "DFLS1100-7" DIOD-POWERDI123-2_V 51.752,36.83 r90 top (schematic designator D1400)
D1401_1 "SMAJ85A-E3/61" VISH-DO-214AC-2_L 125.095,59.69 r270 top (schematic designator D1401)
D1401_2 "SMAJ85A-E3/61" VISH-DO-214AC-2_L 70.802,59.69 r270 top (schematic designator D1401)
Designator5 "Comment" Hole_3.2_Iso 155,5 r0 top locked
Designator6 "Comment" Hole_3.2_Iso 5,95 r0 top locked
Designator7 "Comment" Hole_3.2_Iso 155,95 r0 top locked
Designator8 "Comment" Hole_3.2_Iso 5,5 r0 top locked
Designator11 "Comment" Fiducial_2 10,95 r0 top
Designator12 "Comment" Fiducial_2 155,10 r0 top
F300 "fuse_0.5A_0448.500MR" LITTLEFUSE_448 112.375,17.45 r90 top locked
F301 "fuse_0.25A_0466.250NR" LITTLEFUSE_466 115.57,14.922 r90 top locked
F302 "fuse_0.25A_0466.250NR" LITTLEFUSE_466 117.475,20.002 r90 top locked
F303 "fuse_0.25A_0466.250NR" LITTLEFUSE_466 119.38,14.922 r90 top locked
F304 "fuse_0.25A_0466.250NR" LITTLEFUSE_466 121.285,20.002 r90 top locked
F305 "fuse_0.25A_0466.250NR" LITTLEFUSE_466 123.19,14.922 r90 top locked
F306 "fuse_0.25A_0466.250NR" LITTLEFUSE_466 125.095,20.002 r90 top locked
F307 "fuse_0.25A_0466.250NR" LITTLEFUSE_466 127,14.922 r90 top locked
F308 "fuse_0.25A_0466.250NR" LITTLEFUSE_466 128.905,20.002 r90 top locked
F309 "fuse_0.25A_0466.250NR" LITTLEFUSE_466 130.81,14.922 r90 top locked
F310 "fuse_0.25A_0466.250NR" LITTLEFUSE_466 132.715,20.002 r90 top locked
F311 "fuse_0.25A_0466.250NR" LITTLEFUSE_466 134.62,14.922 r90 top locked
F312 "fuse_0.25A_0466.250NR" LITTLEFUSE_466 136.525,20.002 r90 top locked
F313 "fuse_0.25A_0466.250NR" LITTLEFUSE_466 138.43,14.922 r90 top locked
F314 "fuse_0.25A_0466.250NR" LITTLEFUSE_466 140.335,20.002 r90 top locked
F315 "fuse_0.25A_0466.250NR" LITTLEFUSE_466 142.24,14.922 r90 top locked
F316 "fuse_0.25A_0466.250NR" LITTLEFUSE_466 144.145,20.002 r90 top locked
F317 "fuse_0.25A_0466.250NR" LITTLEFUSE_466 146.05,14.922 r90 top locked
F318 "fuse_0.25A_0466.250NR" LITTLEFUSE_466 147.955,20.002 r90 top locked
F319 "fuse_0.25A_0466.250NR" LITTLEFUSE_466 149.86,14.922 r90 top locked
F320 "fuse_0.5A_0448.500MR" LITTLEFUSE_448 153.035,17.462 r90 top locked
F900 "fuse_1.25A_04661.25NR" LITTLEFUSE_466 6.33,17.462 r90 top locked
IC100_1 "ADG728BRUZ" ADI-RU-16_M 97.314,22.225 r180 top locked (schematic designator IC100)
IC100_2 "ADG728BRUZ" ADI-RU-16_M 68.739,22.225 r180 top locked (schematic designator IC100)
IC101_1 "ADG728BRUZ" ADI-RU-16_M 8.89,65.087 r180 top (schematic designator IC101)
IC101_2 "ADG728BRUZ" ADI-RU-16_M 8.89,57.468 r180 top (schematic designator IC101)
IC104_1 "ADG728BRUZ" ADI-RU-16_M 19.05,65.087 r180 top (schematic designator IC104)
IC104_2 "ADG728BRUZ" ADI-RU-16_M 19.05,57.468 r180 top (schematic designator IC104)
IC800_1 "MCP9800A0T-M/OT" SOT-23-OT5_L 101.6,47.625 r270 top locked (schematic designator IC800)
IC800_2 "MCP9800A0T-M/OT" SOT-23-OT5_L 46.038,47.625 r270 top locked (schematic designator IC800)
IC801_1 "M24M02-DWMN3TP/K" SOIC127P600X175-8N 150.177,48.419 r270 top (schematic designator IC801)
IC801_2 "M24M02-DWMN3TP/K" SOIC127P600X175-8N 97.135,48.68 r270 top (schematic designator IC801)
IC900 "LT8302HS8E#PBF" LT-S8E-8_V 16.192,84.772 r0 top locked
IC1400_1 "LTC6813HLWE-1#3ZZPBF" TSQFP50P1200X1200X160_HS-65N 136.207,49.847 r0 top (schematic designator IC1400)
IC1400_2 "LTC6813HLWE-1#3ZZPBF" TSQFP50P1200X1200X160_HS-65N 82.867,49.847 r0 top locked (schematic designator IC1400)
L600_1 "220µH" TYS6045221M-10 122.428,52.705 r0 top (schematic designator L600)
L600_2 "220µH" TYS6045221M-10 67.818,52.705 r0 top locked (schematic designator L600)
L900 "74404042100" "WE-LQS 4018" 7.144,74.93 r180 top
LD1400_1 "green" LEDC1608X07N 138.43,63.817 r0 top locked (schematic designator LD1400)
LD1400_2 "green" LEDC1608X07N 84.772,63.817 r0 top locked (schematic designator LD1400)
Q600_1 "PBSS4112PANP" PBSS4112PANP 105.093,44.133 r180 top (schematic designator Q600)
Q600_2 "PBSS4112PANP" PBSS4112PANP 50.482,43.815 r180 top (schematic designator Q600)
R100_1 "10k" RESC1608X05N 86.253,12.061 r180 top locked (schematic designator R100)
R100_2 "10k" RESC1608X05N 57.631,12.035 r180 top locked (schematic designator R100)
R101_1 "10k" RESC1608X05N 89.253,12.061 r180 top locked (schematic designator R101)
R101_2 "10k" RESC1608X05N 60.631,12.035 r180 top locked (schematic designator R101)
R102_1 "10k" RESC1608X05N 92.253,12.061 r180 top locked (schematic designator R102)
R102_2 "10k" RESC1608X05N 63.631,12.035 r180 top locked (schematic designator R102)
R103_1 "10k" RESC1608X05N 95.253,12.061 r180 top locked (schematic designator R103)
R103_2 "10k" RESC1608X05N 66.632,12.035 r180 top locked (schematic designator R103)
R104_1 "10k" RESC1608X05N 98.253,12.061 r180 top locked (schematic designator R104)
R104_2 "10k" RESC1608X05N 69.632,12.035 r180 top locked (schematic designator R104)
R105_1 "10k" RESC1608X05N 101.253,12.061 r180 top locked (schematic designator R105)
R105_2 "10k" RESC1608X05N 72.632,12.035 r180 top locked (schematic designator R105)
R106_1 "10k" RESC1608X05N 104.253,12.061 r180 top locked (schematic designator R106)
R106_2 "10k" RESC1608X05N 75.632,12.035 r180 top locked (schematic designator R106)
R107_1 "10k" RESC1608X05N 107.253,12.061 r180 top locked (schematic designator R107)
R107_2 "10k" RESC1608X05N 78.632,12.035 r180 top locked (schematic designator R107)
R108_1 "100R" RESC1608X05N 104.934,24.606 r0 top (schematic designator R108)
R108_2 "100R" RESC1608X05N 76.359,24.606 r0 top (schematic designator R108)
R109_1 "100R" RESC1608X05N 25.717,66.04 r0 top locked (schematic designator R109)
R109_2 "100R" RESC1608X05N 25.697,58.725 r0 top locked (schematic designator R109)
R110_1 "0R" RESC1608X05N 105.249,18.347 r180 top (schematic designator R110)
R110_2 "0R" RESC1608X05N 76.674,18.256 r180 top (schematic designator R110)
R111_1 "0R" RESC1608X05N 29.845,62.938 r270 top (schematic designator R111)
R111_2 "0R" RESC1608X05N 24.447,53.657 r180 top (schematic designator R111)
R112_1 "100R" RESC1608X05N 103.029,14.287 r270 top (schematic designator R112)
R112_2 "100R" RESC1608X05N 74.454,14.287 r270 top (schematic designator R112)
R113_1 "100R" RESC1608X05N 101.441,14.287 r270 top (schematic designator R113)
R113_2 "100R" RESC1608X05N 72.866,14.287 r270 top (schematic designator R113)
R114_1 "100R" RESC1608X05N 99.854,14.287 r270 top (schematic designator R114)
R114_2 "100R" RESC1608X05N 71.279,14.287 r270 top (schematic designator R114)
R115_1 "100R" RESC1608X05N 98.266,14.287 r270 top (schematic designator R115)
R115_2 "100R" RESC1608X05N 69.691,14.287 r270 top (schematic designator R115)
R116_1 "100R" RESC1608X05N 96.679,14.287 r270 top (schematic designator R116)
R116_2 "100R" RESC1608X05N 68.104,14.287 r270 top (schematic designator R116)
R117_1 "100R" RESC1608X05N 95.091,14.287 r270 top (schematic designator R117)
R117_2 "100R" RESC1608X05N 66.516,14.287 r270 top (schematic designator R117)
R118_1 "100R" RESC1608X05N 93.504,14.287 r270 top (schematic designator R118)
R118_2 "100R" RESC1608X05N 64.929,14.287 r270 top (schematic designator R118)
R119_1 "100R" RESC1608X05N 91.916,14.287 r270 top (schematic designator R119)
R119_2 "100R" RESC1608X05N 63.341,14.287 r270 top (schematic designator R119)
R600_1 "124k" RESC1608X05N 107.315,49.847 r90 top locked (schematic designator R600)
R600_2 "124k" RESC1608X05N 52.705,49.847 r90 top locked (schematic designator R600)
R601_1 "10k" RESC1608X05N 109.855,47.625 r0 top locked (schematic designator R601)
R601_2 "10k" RESC1608X05N 55.245,47.625 r0 top locked (schematic designator R601)
R602_1 "1k5" RESC1608X05N 122.237,48.578 r180 top locked (schematic designator R602)
R602_2 "1k5" RESC1608X05N 67.627,48.578 r180 top locked (schematic designator R602)
R603_1 "1k" RESC1608X05N 119.38,48.578 r180 top (schematic designator R603)
R603_2 "1k" RESC1608X05N 64.77,48.578 r180 top (schematic designator R603)
R604_1 "1R" RESC2012X05N 127.254,51.054 r270 top (schematic designator R604)
R604_2 "1R" RESC2012X05N 72.644,51.117 r270 top locked (schematic designator R604)
R605_1 "10k" RESC1608X05N 108.585,44.133 r90 top (schematic designator R605)
R605_2 "10k" RESC1608X05N 53.975,43.815 r90 top (schematic designator R605)
R606_1 "124k" RESC1608X05N 107.315,44.133 r90 top (schematic designator R606)
R606_2 "124k" RESC1608X05N 52.705,43.815 r90 top (schematic designator R606)
R607_1 "10k" RESC1608X05N 101.6,44.133 r90 top (schematic designator R607)
R607_2 "10k" RESC1608X05N 46.988,43.815 r90 top (schematic designator R607)
R608_1 "68k" RESC1608X05N 104.14,42.227 r180 top (schematic designator R608)
R608_2 "68k" RESC1608X05N 48.895,41.593 r180 top (schematic designator R608)
R609_1 "0R" RESC1608X05N 105.093,46.038 r180 top (schematic designator R609)
R609_2 "0R" RESC1608X05N 50.482,45.72 r180 top (schematic designator R609)
R610_1 "0R" RESC1608X05N 109.855,45.72 r270 top (schematic designator R610)
R610_2 "0R" RESC1608X05N 55.245,45.72 r270 top (schematic designator R610)
R700_1 "10k" RESC1608X05N 91.99,22.861 r90 top locked (schematic designator R700)
R700_2 "10k" RESC1608X05N 63.317,22.835 r90 top locked (schematic designator R700)
R701_1 "10k" RESC1608X05N 90.402,22.861 r90 top locked (schematic designator R701)
R701_2 "10k" RESC1608X05N 61.73,22.835 r90 top locked (schematic designator R701)
R702_1 "10k" RESC1608X05N 88.815,22.861 r90 top locked (schematic designator R702)
R702_2 "10k" RESC1608X05N 60.142,22.835 r90 top locked (schematic designator R702)
R703_1 "10k" RESC1608X05N 87.227,22.861 r90 top locked (schematic designator R703)
R703_2 "10k" RESC1608X05N 58.555,22.835 r90 top locked (schematic designator R703)
R704_1 "10k" RESC1608X05N 85.64,22.861 r90 top locked (schematic designator R704)
R704_2 "10k" RESC1608X05N 56.967,22.835 r90 top locked (schematic designator R704)
R705_1 "10k" RESC1608X05N 84.052,22.861 r90 top locked (schematic designator R705)
R705_2 "10k" RESC1608X05N 55.38,22.835 r90 top locked (schematic designator R705)
R706_1 "10k" RESC1608X05N 82.465,22.861 r90 top locked (schematic designator R706)
R706_2 "10k" RESC1608X05N 53.792,22.835 r90 top locked (schematic designator R706)
R707_1 "10k" RESC1608X05N 80.877,22.861 r90 top locked (schematic designator R707)
R707_2 "10k" RESC1608X05N 52.205,22.835 r90 top locked (schematic designator R707)
R708_1 "10k" RESC1608X05N 88.9,15.557 r90 top locked (schematic designator R708)
R708_2 "10k" RESC1608X05N 59.531,16.351 r90 top locked (schematic designator R708)
R800_1 "10k" RESC1608X05N 101.282,50.482 r0 top (schematic designator R800)
R800_2 "10k" RESC1608X05N 46.038,50.482 r0 top (schematic designator R800)
R801_1 "10k" RESC1608X05N 152.559,42.513 r0 top (schematic designator R801)
R801_2 "10k" RESC1608X05N 99.357,42.545 r0 top locked (schematic designator R801)
R900 "390k" RESC1608X05N 11.43,86.995 r180 top
R901 "86k6" RESC1608X05N 11.43,88.582 r0 top
R902 "115k" RESC1608X05N 20.32,86.36 r270 top
R903 "39R" RESC2012X05N 19.367,92.392 r180 top locked
R904 "220k" RESC1608X05N 20.32,83.502 r270 top
R905 "10k" RESC1608X05N 18.098,88.582 r0 top
R1100 "150R" RESC1608X05N 105.727,66.345 r270 top
R1101 "150R" RESC1608X05N 108.267,66.345 r270 top
R1102 "150R" RESC1608X05N 129.54,67.88 r270 top
R1103 "150R" RESC1608X05N 135.255,67.88 r270 top
R1104 "150R" RESC1608X05N 140.97,67.88 r270 top
R1105 "150R" RESC1608X05N 146.685,67.88 r270 top
R1106 "150R" RESC1608X05N 83.82,67.88 r270 top
R1107 "150R" RESC1608X05N 89.535,67.88 r270 top
R1108 "150R" RESC1608X05N 95.25,67.88 r270 top
R1109 "150R" RESC1608X05N 99.235,67.88 r270 top
R1110 "150R" RESC1608X05N 100.642,66.358 r270 top
R1111 "150R" RESC1608X05N 103.188,66.345 r270 top
R1112 "150R" RESC1608X05N 39.052,66.358 r270 top
R1113 "150R" RESC1608X05N 42.227,66.358 r270 top
R1114 "150R" RESC1608X05N 45.402,66.345 r270 top
R1115 "150R" RESC1608X05N 48.578,66.358 r270 top
R1116 "150R" RESC1608X05N 51.752,66.358 r270 top
R1117 "150R" RESC1608X05N 54.927,66.358 r270 top
R1118 "10k" RESC1608X05N 122.687,60.642 r90 top
R1300_1 "100R" RESC1608X05N 136.505,29.833 r90 top (schematic designator R1300)
R1300_2 "100R" RESC1608X05N 83.165,29.833 r90 top (schematic designator R1300)
R1301_1 "100R" RESC1608X05N 139.045,29.833 r90 top (schematic designator R1301)
R1301_2 "100R" RESC1608X05N 85.705,29.833 r90 top (schematic designator R1301)
R1302_1 "100R" RESC1608X05N 141.585,29.833 r90 top (schematic designator R1302)
R1302_2 "100R" RESC1608X05N 88.245,29.833 r90 top (schematic designator R1302)
R1303_1 "100R" RESC1608X05N 144.125,29.833 r90 top (schematic designator R1303)
R1303_2 "100R" RESC1608X05N 90.785,29.833 r90 top (schematic designator R1303)
R1304_1 "100R" RESC1608X05N 146.665,29.833 r90 top (schematic designator R1304)
R1304_2 "100R" RESC1608X05N 93.325,29.833 r90 top (schematic designator R1304)
R1305_1 "100R" RESC1608X05N 149.205,29.833 r90 top (schematic designator R1305)
R1305_2 "100R" RESC1608X05N 95.865,29.833 r90 top (schematic designator R1305)
R1306_1 "100R" RESC1608X05N 151.745,29.833 r90 top (schematic designator R1306)
R1306_2 "100R" RESC1608X05N 98.405,29.833 r90 top (schematic designator R1306)
R1307_1 "100R" RESC1608X05N 121.265,29.833 r90 top (schematic designator R1307)
R1307_2 "100R" RESC1608X05N 67.925,29.833 r90 top (schematic designator R1307)
R1308_1 "100R" RESC1608X05N 123.805,29.833 r90 top (schematic designator R1308)
R1308_2 "100R" RESC1608X05N 70.465,29.833 r90 top (schematic designator R1308)
R1309_1 "100R" RESC1608X05N 126.345,29.833 r90 top (schematic designator R1309)
R1309_2 "100R" RESC1608X05N 73.005,29.833 r90 top (schematic designator R1309)
R1310_1 "100R" RESC1608X05N 128.885,29.833 r90 top (schematic designator R1310)
R1310_2 "100R" RESC1608X05N 75.545,29.833 r90 top (schematic designator R1310)
R1311_1 "100R" RESC1608X05N 131.425,29.833 r90 top (schematic designator R1311)
R1311_2 "100R" RESC1608X05N 78.085,29.833 r90 top (schematic designator R1311)
R1312_1 "100R" RESC1608X05N 133.965,29.833 r90 top (schematic designator R1312)
R1312_2 "100R" RESC1608X05N 80.625,29.833 r90 top (schematic designator R1312)
R1313_1 "100R" RESC1608X05N 106.045,29.845 r90 top (schematic designator R1313)
R1313_2 "100R" RESC1608X05N 52.705,29.845 r90 top (schematic designator R1313)
R1314_1 "100R" RESC1608X05N 108.585,29.845 r90 top (schematic designator R1314)
R1314_2 "100R" RESC1608X05N 55.245,29.845 r90 top (schematic designator R1314)
R1315_1 "100R" RESC1608X05N 111.125,29.845 r90 top (schematic designator R1315)
R1315_2 "100R" RESC1608X05N 57.785,29.845 r90 top (schematic designator R1315)
R1316_1 "100R" RESC1608X05N 113.665,29.845 r90 top (schematic designator R1316)
R1316_2 "100R" RESC1608X05N 60.325,29.845 r90 top (schematic designator R1316)
R1317_1 "100R" RESC1608X05N 116.205,29.845 r90 top (schematic designator R1317)
R1317_2 "100R" RESC1608X05N 62.865,29.845 r90 top (schematic designator R1317)
R1318_1 "100R" RESC1608X05N 118.745,29.845 r90 top (schematic designator R1318)
R1318_2 "100R" RESC1608X05N 65.405,29.845 r90 top (schematic designator R1318)
R1400_1 "1k2" RESC1608X05N 133.985,58.837 r90 top locked (schematic designator R1400)
R1400_2 "1k2" RESC1608X05N 80.328,58.788 r90 top locked (schematic designator R1400)
R1401_1 "100R" RESC2012X05N 127.635,59.69 r270 top (schematic designator R1401)
R1401_2 "100R" RESC2012X05N 73.66,59.69 r270 top locked (schematic designator R1401)
R1402_1 "820R" RESC1608X05N 135.496,58.837 r270 top locked (schematic designator R1402)
R1402_2 "820R" RESC1608X05N 81.915,58.788 r270 top locked (schematic designator R1402)
R1403_1 "270R" RESC1608X05N 135.78,63.818 r0 top (schematic designator R1403)
R1403_2 "270R" RESC1608X05N 82.074,63.817 r0 top (schematic designator R1403)
R1404_1 "1M" RESC1608X05N 136.93,58.837 r90 top locked (schematic designator R1404)
R1404_2 "1M" RESC1608X05N 83.502,58.788 r90 top locked (schematic designator R1404)
R1405_1 "120R" RESC1608X05N 40.957,29.21 r0 top (schematic designator R1405)
R1405_2 "120R" RESC1608X05N 25.082,29.21 r0 top (schematic designator R1405)
R1406_1 "0R" RESC1608X05N 132.08,58.737 r90 top locked (schematic designator R1406)
R1406_2 "0R" RESC1608X05N 78.422,58.788 r90 top locked (schematic designator R1406)
R1407_1 "0R" RESC1608X05N 132.08,61.436 r90 top (schematic designator R1407)
R1407_2 "0R" RESC1608X05N 78.422,61.436 r90 top (schematic designator R1407)
R1408_1 "0R" RESC1608X05N 145.732,61.119 r180 top (schematic designator R1408)
R1408_2 "0R" RESC1608X05N 92.392,61.119 r180 top (schematic designator R1408)
R1409_1 "0R" RESC1608X05N 145.732,58.261 r180 top locked (schematic designator R1409)
R1409_2 "0R" RESC1608X05N 92.392,58.261 r180 top locked (schematic designator R1409)
R1410_1 "0R" RESC1608X05N 145.732,56.515 r180 top locked (schematic designator R1410)
R1410_2 "0R" RESC1608X05N 92.392,56.515 r180 top locked (schematic designator R1410)
R1411_1 "0R" RESC1608X05N 145.732,55.34 r180 top (schematic designator R1411)
R1411_2 "0R" RESC1608X05N 92.392,55.086 r180 top locked (schematic designator R1411)
R1412_1 "0R" RESC1608X05N 145.732,53.34 r180 top locked (schematic designator R1412)
R1412_2 "0R" RESC1608X05N 92.392,53.34 r180 top locked (schematic designator R1412)
R1413_1 "0R" RESC1608X05N 145.732,51.911 r180 top locked (schematic designator R1413)
R1413_2 "0R" RESC1608X05N 92.392,51.911 r180 top locked (schematic designator R1413)
R1414_1 "0R" RESC1608X05N 145.732,50.006 r180 top locked (schematic designator R1414)
R1414_2 "0R" RESC1608X05N 92.392,50.165 r180 top locked (schematic designator R1414)
R1415_1 "0R" RESC1608X05N 145.732,48.578 r180 top locked (schematic designator R1415)
R1415_2 "0R" RESC1608X05N 92.392,48.736 r180 top locked (schematic designator R1415)
R1416_1 "0R" RESC1608X05N 145.732,46.915 r180 top locked (schematic designator R1416)
R1416_2 "0R" RESC1608X05N 92.372,46.97 r180 top locked (schematic designator R1416)
R1417_1 "0R" RESC1608X05N 145.732,45.402 r180 top locked (schematic designator R1417)
R1417_2 "0R" RESC1608X05N 92.372,45.605 r180 top locked (schematic designator R1417)
R1418_1 "120R" RESC1608X05N 34.925,29.21 r0 top (schematic designator R1418)
R1418_2 "120R" RESC1608X05N 19.05,29.21 r0 top (schematic designator R1418)
R1419_1 "1k2" RESC1608X05N 148.273,53.499 r90 top (schematic designator R1419)
R1419_2 "1k2" RESC1608X05N 95.135,53.734 r90 top (schematic designator R1419)
R1420_1 "1k2" RESC1608X05N 150.336,53.499 r90 top (schematic designator R1420)
R1420_2 "1k2" RESC1608X05N 97.223,53.737 r90 top (schematic designator R1420)
R1421_1 "10k" RESC1608X05N 154.686,47.879 r90 top (schematic designator R1421)
R1421_2 "10k" RESC1608X05N 74.93,53.721 r180 top (schematic designator R1421)
R1422_1 "10k" RESC1608X05N 154.686,51.244 r90 top (schematic designator R1422)
R1422_2 "10k" RESC1608X05N 74.93,55.118 r180 top (schematic designator R1422)
R1423_1 "10k" RESC1608X05N 152.432,52.665 r180 top (schematic designator R1423)
R1423_2 "10k" RESC1608X05N 74.93,56.515 r180 top (schematic designator R1423)
R1424_1 "10k" RESC1608X05N 152.432,54.199 r180 top (schematic designator R1424)
R1424_2 "10k" RESC1608X05N 89.725,55.452 r90 top (schematic designator R1424)
R1425_1 "10k" RESC1608X05N 15.748,30.861 r90 top (schematic designator R1425)
R1425_2 "10k" RESC1608X05N 10.287,30.861 r90 top (schematic designator R1425)
R1426_1 "10k" RESC1608X05N 14.351,30.861 r90 top (schematic designator R1426)
R1426_2 "10k" RESC1608X05N 8.89,30.861 r90 top (schematic designator R1426)
R1427_1 "10k" RESC1608X05N 12.954,30.861 r90 top (schematic designator R1427)
R1427_2 "10k" RESC1608X05N 7.493,30.861 r90 top (schematic designator R1427)
R1500 "130R" RESC5025X07N 117.505,79.375 r270 top
R1501 "130R" RESC5025X07N 123.19,79.375 r270 top
R1502 "130R" RESC5025X07N 128.905,79.375 r270 top
R1503 "130R" RESC5025X07N 134.62,79.375 r270 top
R1504 "130R" RESC5025X07N 140.335,79.375 r270 top
R1505 "130R" RESC5025X07N 146.05,79.375 r270 top
R1506 "130R" RESC5025X07N 117.475,90.805 r90 top locked
R1507 "130R" RESC5025X07N 123.19,90.805 r90 top locked
R1508 "130R" RESC5025X07N 128.905,90.805 r90 top
R1509 "130R" RESC5025X07N 134.62,90.805 r90 top locked
R1510 "130R" RESC5025X07N 140.315,90.805 r90 top locked
R1511 "130R" RESC5025X07N 146.05,90.805 r90 top locked
R1512 "3k3" RESC1608X05N 115.252,70.485 r270 top locked
R1513 "3k3" RESC1608X05N 120.968,70.485 r270 top locked
R1514 "3k3" RESC1608X05N 126.682,70.485 r270 top locked
R1515 "3k3" RESC1608X05N 132.398,70.485 r270 top locked
R1516 "3k3" RESC1608X05N 138.112,70.485 r270 top locked
R1517 "3k3" RESC1608X05N 143.918,70.485 r270 top
R1518 "130R" RESC5025X07N 83.185,79.375 r270 top
R1519 "130R" RESC5025X07N 88.9,79.375 r270 top
R1520 "130R" RESC5025X07N 94.615,79.375 r270 top
R1521 "130R" RESC5025X07N 100.33,79.375 r270 top
R1522 "130R" RESC5025X07N 106.045,79.375 r270 top
R1523 "130R" RESC5025X07N 111.76,79.375 r270 top
R1524 "130R" RESC5025X07N 83.185,90.805 r90 top locked
R1525 "130R" RESC5025X07N 88.9,90.805 r90 top locked
R1526 "130R" RESC5025X07N 94.615,90.805 r90 top locked
R1527 "130R" RESC5025X07N 100.33,90.805 r90 top locked
R1528 "130R" RESC5025X07N 106.045,90.805 r90 top locked
R1529 "130R" RESC5025X07N 111.76,90.805 r90 top locked
R1530 "3k3" RESC1608X05N 80.962,70.485 r270 top locked
R1531 "3k3" RESC1608X05N 86.677,70.485 r270 top locked
R1532 "3k3" RESC1608X05N 92.392,70.485 r270 top locked
R1533 "3k3" RESC1608X05N 98.108,70.485 r270 top locked
R1534 "3k3" RESC1608X05N 103.822,70.485 r270 top locked
R1535 "3k3" RESC1608X05N 109.537,70.485 r270 top locked
R1536 "130R" RESC5025X07N 48.895,79.375 r270 top
R1537 "130R" RESC5025X07N 54.61,79.375 r270 top
R1538 "130R" RESC5025X07N 60.325,79.375 r270 top
R1539 "130R" RESC5025X07N 66.04,79.375 r270 top
R1540 "130R" RESC5025X07N 71.755,79.375 r270 top
R1541 "130R" RESC5025X07N 77.465,79.375 r270 top
R1542 "130R" RESC5025X07N 48.895,90.805 r90 top locked
R1543 "130R" RESC5025X07N 54.61,90.805 r90 top locked
R1544 "130R" RESC5025X07N 60.325,90.805 r90 top locked
R1545 "130R" RESC5025X07N 66.04,90.805 r90 top locked
R1546 "130R" RESC5025X07N 71.755,90.805 r90 top locked
R1547 "130R" RESC5025X07N 77.45,90.805 r90 top locked
R1548 "3k3" RESC1608X05N 46.672,70.485 r270 top locked
R1549 "3k3" RESC1608X05N 52.387,70.485 r270 top locked
R1550 "3k3" RESC1608X05N 58.102,70.485 r270 top locked
R1551 "3k3" RESC1608X05N 63.817,70.485 r270 top locked
R1552 "3k3" RESC1608X05N 69.532,70.485 r270 top locked
R1553 "3k3" RESC1608X05N 75.248,70.485 r270 top locked
SJ300 "0R" RESC1608X05N 112.415,12.395 r0 top
SJ301 "0R" RESC1608X05N 153.035,12.383 r0 top
T1500 "NX2301P,215" NXP-SOT23_N 118.11,71.12 r90 top
T1501 "NX2301P,215" NXP-SOT23_N 123.825,71.12 r90 top
T1502 "NX2301P,215" NXP-SOT23_N 129.54,71.12 r90 top locked
T1503 "NX2301P,215" NXP-SOT23_N 135.267,71.12 r90 top
T1504 "NX2301P,215" NXP-SOT23_N 140.97,71.12 r90 top
T1505 "NX2301P,215" NXP-SOT23_N 146.685,71.12 r90 top
T1506 "NX2301P,215" NXP-SOT23_N 83.82,71.12 r90 top
T1507 "NX2301P,215" NXP-SOT23_N 89.535,71.12 r90 top
T1508 "NX2301P,215" NXP-SOT23_N 95.25,71.12 r90 top
T1509 "NX2301P,215" NXP-SOT23_N 100.98,71.12 r90 top
T1510 "NX2301P,215" NXP-SOT23_N 106.66,71.12 r90 top
T1511 "NX2301P,215" NXP-SOT23_N 112.395,71.12 r90 top
T1512 "NX2301P,215" NXP-SOT23_N 49.53,71.12 r90 top
T1513 "NX2301P,215" NXP-SOT23_N 55.245,71.12 r90 top
T1514 "NX2301P,215" NXP-SOT23_N 60.96,71.12 r90 top
T1515 "NX2301P,215" NXP-SOT23_N 66.675,71.12 r90 top
T1516 "NX2301P,215" NXP-SOT23_N 72.39,71.12 r90 top
T1517 "NX2301P,215" NXP-SOT23_N 78.105,71.12 r90 top
TP900 "Testpoint_Square" Testpoint_S1 12.383,22.225 r90 top locked
TP901 "Testpoint_Square" Testpoint_S1 9.842,22.225 r90 top locked
TP902 "Testpoint_Square" Testpoint_S1 44.926,72.866 r90 top
TP903 "Testpoint_Square" Testpoint_S1 43.18,72.866 r90 top
TP1400_1 "Testpoint_Square" Testpoint_S1 132.398,63.817 r180 top (schematic designator TP1400)
TP1400_2 "Testpoint_Square" Testpoint_S1 78.74,63.817 r180 top (schematic designator TP1400)
TP1401_1 "Testpoint_Square" Testpoint_S1 148.887,59.214 r0 top (schematic designator TP1401)
TP1401_2 "Testpoint_Square" Testpoint_S1 95.567,59.214 r180 top (schematic designator TP1401)
TP1402_1 "Testpoint_Square" Testpoint_S1 148.907,60.642 r0 top (schematic designator TP1402)
TP1402_2 "Testpoint_Square" Testpoint_S1 95.567,60.642 r180 top (schematic designator TP1402)
TP1403_1 "Testpoint_Square" Testpoint_S1 140.97,63.817 r180 top (schematic designator TP1403)
TP1403_2 "Testpoint_Square" Testpoint_S1 87.312,63.817 r0 top (schematic designator TP1403)
TP1404_1 "Testpoint_Square" Testpoint_S1 51.435,10.954 r90 top locked (schematic designator TP1404)
TP1404_2 "Testpoint_Square" Testpoint_S1 36.512,10.954 r90 top locked (schematic designator TP1404)
TP1405_1 "Testpoint_Square" Testpoint_S1 48.59,10.954 r90 top locked (schematic designator TP1405)
TP1405_2 "Testpoint_Square" Testpoint_S1 33.387,10.954 r90 top locked (schematic designator TP1405)
TP1406_1 "Testpoint_Square" Testpoint_S1 40.957,10.954 r90 top locked (schematic designator TP1406)
TP1406_2 "Testpoint_Square" Testpoint_S1 25.717,10.954 r90 top locked (schematic designator TP1406)
TP1407_1 "Testpoint_Square" Testpoint_S1 43.974,10.954 r90 top locked (schematic designator TP1407)
TP1407_2 "Testpoint_Square" Testpoint_S1 29.19,10.954 r90 top locked (schematic designator TP1407)
TP1408_1 "Testpoint_Square" Testpoint_S1 148.907,57.785 r180 top (schematic designator TP1408)
TP1408_2 "Testpoint_Square" Testpoint_S1 95.567,57.785 r180 top locked (schematic designator TP1408)
TP1409_1 "Testpoint_Square" Testpoint_S1 148.887,56.356 r180 top (schematic designator TP1409)
TP1409_2 "Testpoint_Square" Testpoint_S1 95.567,56.356 r180 top (schematic designator TP1409)
TR900 "WE_750313457" WE_750313457 29.527,86.677 r0 top locked
TR1400_1 "HM2102NL" HM2102NL 37.941,20.637 r90 top locked (schematic designator TR1400)
TR1400_2 "HM2102NL" HM2102NL 22.066,20.637 r90 top locked (schematic designator TR1400)
U100_1 "AD8628ARTZ-R2" ADI-RJ-5_M 104.299,21.431 r270 top (schematic designator U100)
U100_2 "AD8628ARTZ-R2" ADI-RJ-5_M 75.724,21.431 r270 top locked (schematic designator U100)
U101_1 "AD8628ARTZ-R2" ADI-RJ-5_M 26.67,63.182 r0 top locked (schematic designator U101)
U101_2 "AD8628ARTZ-R2" ADI-RJ-5_M 26.67,55.88 r0 top locked (schematic designator U101)
U600_1 "LM5161QPWPRQ1" PWP0014A 112.395,51.435 r0 top (schematic designator U600)
U600_2 "LM5161QPWPRQ1" PWP0014A 57.785,51.435 r0 top (schematic designator U600)
U700_1 "TCA6408APWR" PW0016A_L 84.455,17.462 r180 top locked (schematic designator U700)
U700_2 "TCA6408APWR" PW0016A_L 55.086,18.256 r180 top locked (schematic designator U700)
U1100 "ACPL-217" SOIC127P700X220-4N 104.457,60.642 r270 top locked
U1101 "ACPL-217" SOIC127P700X220-4N 107.632,60.642 r270 top locked
U1102 "ACPL-217" SOIC127P700X220-4N 110.807,60.642 r270 top locked
U1103 "ACPL-217" SOIC127P700X220-4N 113.983,60.642 r270 top locked
U1104 "ACPL-217" SOIC127P700X220-4N 117.157,60.642 r270 top locked
U1105 "ACPL-217" SOIC127P700X220-4N 120.332,60.642 r270 top locked
U1106 "ACPL-217" SOIC127P700X220-4N 57.468,60.642 r270 top locked
U1107 "ACPL-217" SOIC127P700X220-4N 60.642,60.642 r270 top locked
U1108 "ACPL-217" SOIC127P700X220-4N 63.817,60.642 r270 top locked
U1109 "ACPL-217" SOIC127P700X220-4N 66.992,60.642 r270 top locked
U1110 "ACPL-217" SOIC127P700X220-4N 98.108,60.642 r270 top locked
U1111 "ACPL-217" SOIC127P700X220-4N 101.282,60.642 r270 top locked
U1112 "ACPL-217" SOIC127P700X220-4N 38.417,60.642 r270 top locked
U1113 "ACPL-217" SOIC127P700X220-4N 41.593,60.642 r270 top locked
U1114 "ACPL-217" SOIC127P700X220-4N 44.767,60.642 r270 top locked
U1115 "ACPL-217" SOIC127P700X220-4N 47.942,60.642 r270 top locked
U1116 "ACPL-217" SOIC127P700X220-4N 51.117,60.642 r270 top locked
U1117 "ACPL-217" SOIC127P700X220-4N 54.292,60.642 r270 top locked
X200 "molex_microfit_3_12x2_THT" MOLEX_MICROFIT_12x2_THT 131,2.5 r180 top locked
X201 "molex_microfit_3_08x2_THT" MOLEX_MICROFIT_08x2_THT 96.5,2.5 r180 top locked
X202 "molex_microfit_3_08x2_THT" MOLEX_MICROFIT_08x2_THT 68,2.5 r180 top locked
X400 "gen_pinheader_2.54_2x9" Pinheader_2.54_2x9 16.51,42.545 r180 top locked
X401 "gen_pinheader_2.54_2x9" Pinheader_2.54_2x9 16.51,50.165 r180 top locked
X402 "gen_pinheader_2.54_2x5" Pinheader_2.54_2x5 36.83,42.545 r180 top locked
X403 "gen_pinheader_2.54_2x5" Pinheader_2.54_2x5 36.83,50.165 r180 top locked
X404 "gen_pinheader_2.54_2x10" Pinheader_2.54_2x10 17.78,34.925 r180 top locked
X405 "gen_pinheader_2.54_2x4" Pinheader_2.54_2x4 38.1,34.925 r180 top locked
X500 "molex_microfit_3_01x2_THT" MOLEX_MICROFIT_01x2_THT 50,2.5 r180 top locked
X501 "molex_microfit_3_01x2_THT" MOLEX_MICROFIT_01x2_THT 42.5,2.5 r180 top locked
X502 "molex_microfit_3_01x2_THT" MOLEX_MICROFIT_01x2_THT 35,2.5 r180 top locked
X503 "molex_microfit_3_01x2_THT" MOLEX_MICROFIT_01x2_THT 27.5,2.5 r180 top locked
X900 "gen_pinheader_2.54_2" Pinheader_2.54_2 40.322,75.248 r180 top locked
X1000 "samtec_TSW-102-07-G-D" Pinheader_2.54_2x2 11.112,17.462 r0 top locked
X1001 "molex_microfit_3_01x2_THT" MOLEX_MICROFIT_01x2_THT 20,2.5 r180 top locked
X1002 "molex_microfit_3_01x2_THT" MOLEX_MICROFIT_01x2_THT 12.5,2.5 r180 top locked
Z1300_1 "MMSZ4692T1G" ONSC-SOD-123-2-425-04_V 139.045,38.088 r0 top (schematic designator Z1300)
Z1300_2 "MMSZ4692T1G" ONSC-SOD-123-2-425-04_V 85.705,38.088 r0 top (schematic designator Z1300)
Z1301_1 "MMSZ4692T1G" ONSC-SOD-123-2-425-04_V 141.585,35.548 r0 top locked (schematic designator Z1301)
Z1301_2 "MMSZ4692T1G" ONSC-SOD-123-2-425-04_V 88.245,35.548 r0 top locked (schematic designator Z1301)
Z1302_1 "MMSZ4692T1G" ONSC-SOD-123-2-425-04_V 144.125,38.088 r0 top locked (schematic designator Z1302)
Z1302_2 "MMSZ4692T1G" ONSC-SOD-123-2-425-04_V 90.785,38.088 r0 top locked (schematic designator Z1302)
Z1303_1 "MMSZ4692T1G" ONSC-SOD-123-2-425-04_V 146.665,35.548 r0 top locked (schematic designator Z1303)
Z1303_2 "MMSZ4692T1G" ONSC-SOD-123-2-425-04_V 93.325,35.548 r0 top locked (schematic designator Z1303)
Z1304_1 "MMSZ4692T1G" ONSC-SOD-123-2-425-04_V 149.205,38.088 r0 top locked (schematic designator Z1304)
Z1304_2 "MMSZ4692T1G" ONSC-SOD-123-2-425-04_V 95.865,38.088 r0 top locked (schematic designator Z1304)
Z1305_1 "MMSZ4692T1G" ONSC-SOD-123-2-425-04_V 151.745,35.548 r0 top locked (schematic designator Z1305)
Z1305_2 "MMSZ4692T1G" ONSC-SOD-123-2-425-04_V 98.405,35.548 r0 top locked (schematic designator Z1305)
Z1306_1 "MMSZ4692T1G" ONSC-SOD-123-2-425-04_V 123.805,38.088 r0 top (schematic designator Z1306)
Z1306_2 "MMSZ4692T1G" ONSC-SOD-123-2-425-04_V 70.465,38.088 r0 top (schematic designator Z1306)
Z1307_1 "MMSZ4692T1G" ONSC-SOD-123-2-425-04_V 126.345,35.548 r0 top locked (schematic designator Z1307)
Z1307_2 "MMSZ4692T1G" ONSC-SOD-123-2-425-04_V 73.005,35.548 r0 top locked (schematic designator Z1307)
Z1308_1 "MMSZ4692T1G" ONSC-SOD-123-2-425-04_V 128.885,38.088 r0 top locked (schematic designator Z1308)
Z1308_2 "MMSZ4692T1G" ONSC-SOD-123-2-425-04_V 75.545,38.088 r0 top locked (schematic designator Z1308)
Z1309_1 "MMSZ4692T1G" ONSC-SOD-123-2-425-04_V 131.425,35.548 r0 top locked (schematic designator Z1309)
Z1309_2 "MMSZ4692T1G" ONSC-SOD-123-2-425-04_V 78.085,35.548 r0 top locked (schematic designator Z1309)
Z1310_1 "MMSZ4692T1G" ONSC-SOD-123-2-425-04_V 133.965,38.088 r0 top locked (schematic designator Z1310)
Z1310_2 "MMSZ4692T1G" ONSC-SOD-123-2-425-04_V 80.625,38.088 r0 top locked (schematic designator Z1310)
Z1311_1 "MMSZ4692T1G" ONSC-SOD-123-2-425-04_V 136.505,35.548 r0 top locked (schematic designator Z1311)
Z1311_2 "MMSZ4692T1G" ONSC-SOD-123-2-425-04_V 83.165,35.548 r0 top locked (schematic designator Z1311)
